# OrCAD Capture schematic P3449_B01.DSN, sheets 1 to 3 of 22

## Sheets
1 0021_Loop Back Test: size Custom
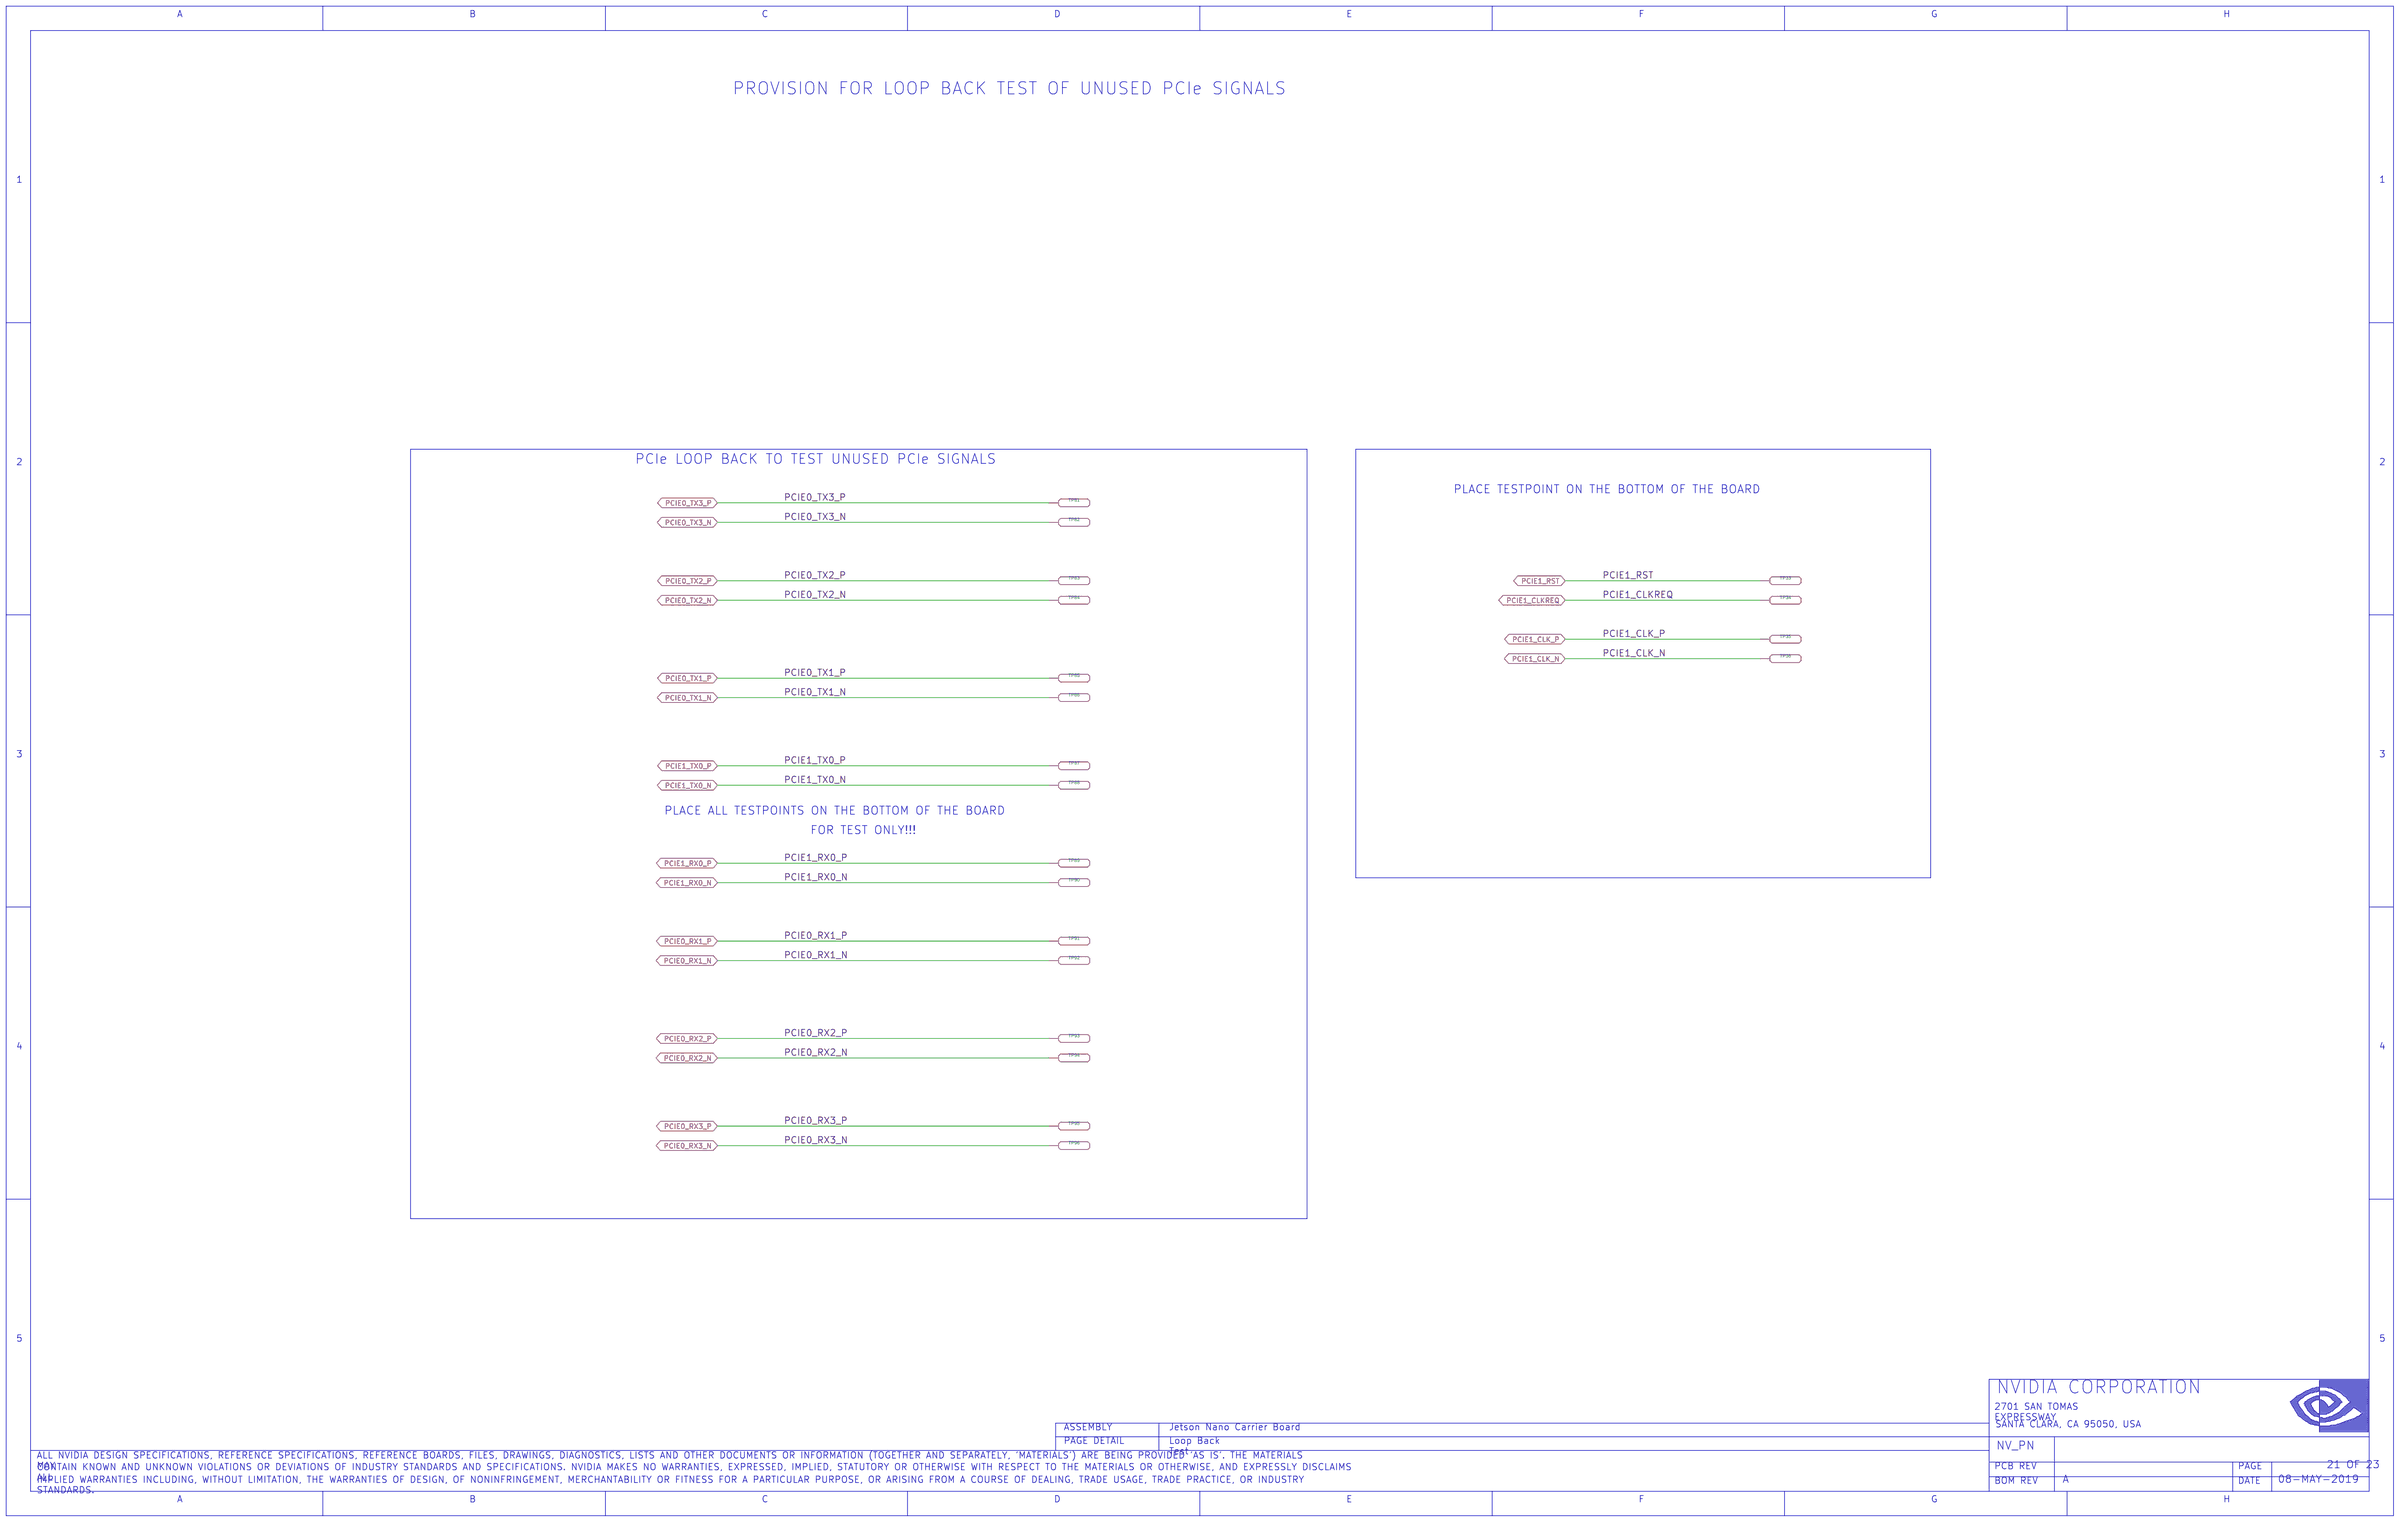
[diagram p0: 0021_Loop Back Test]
2 0020_Fan, Debug and EEPROM: size Custom
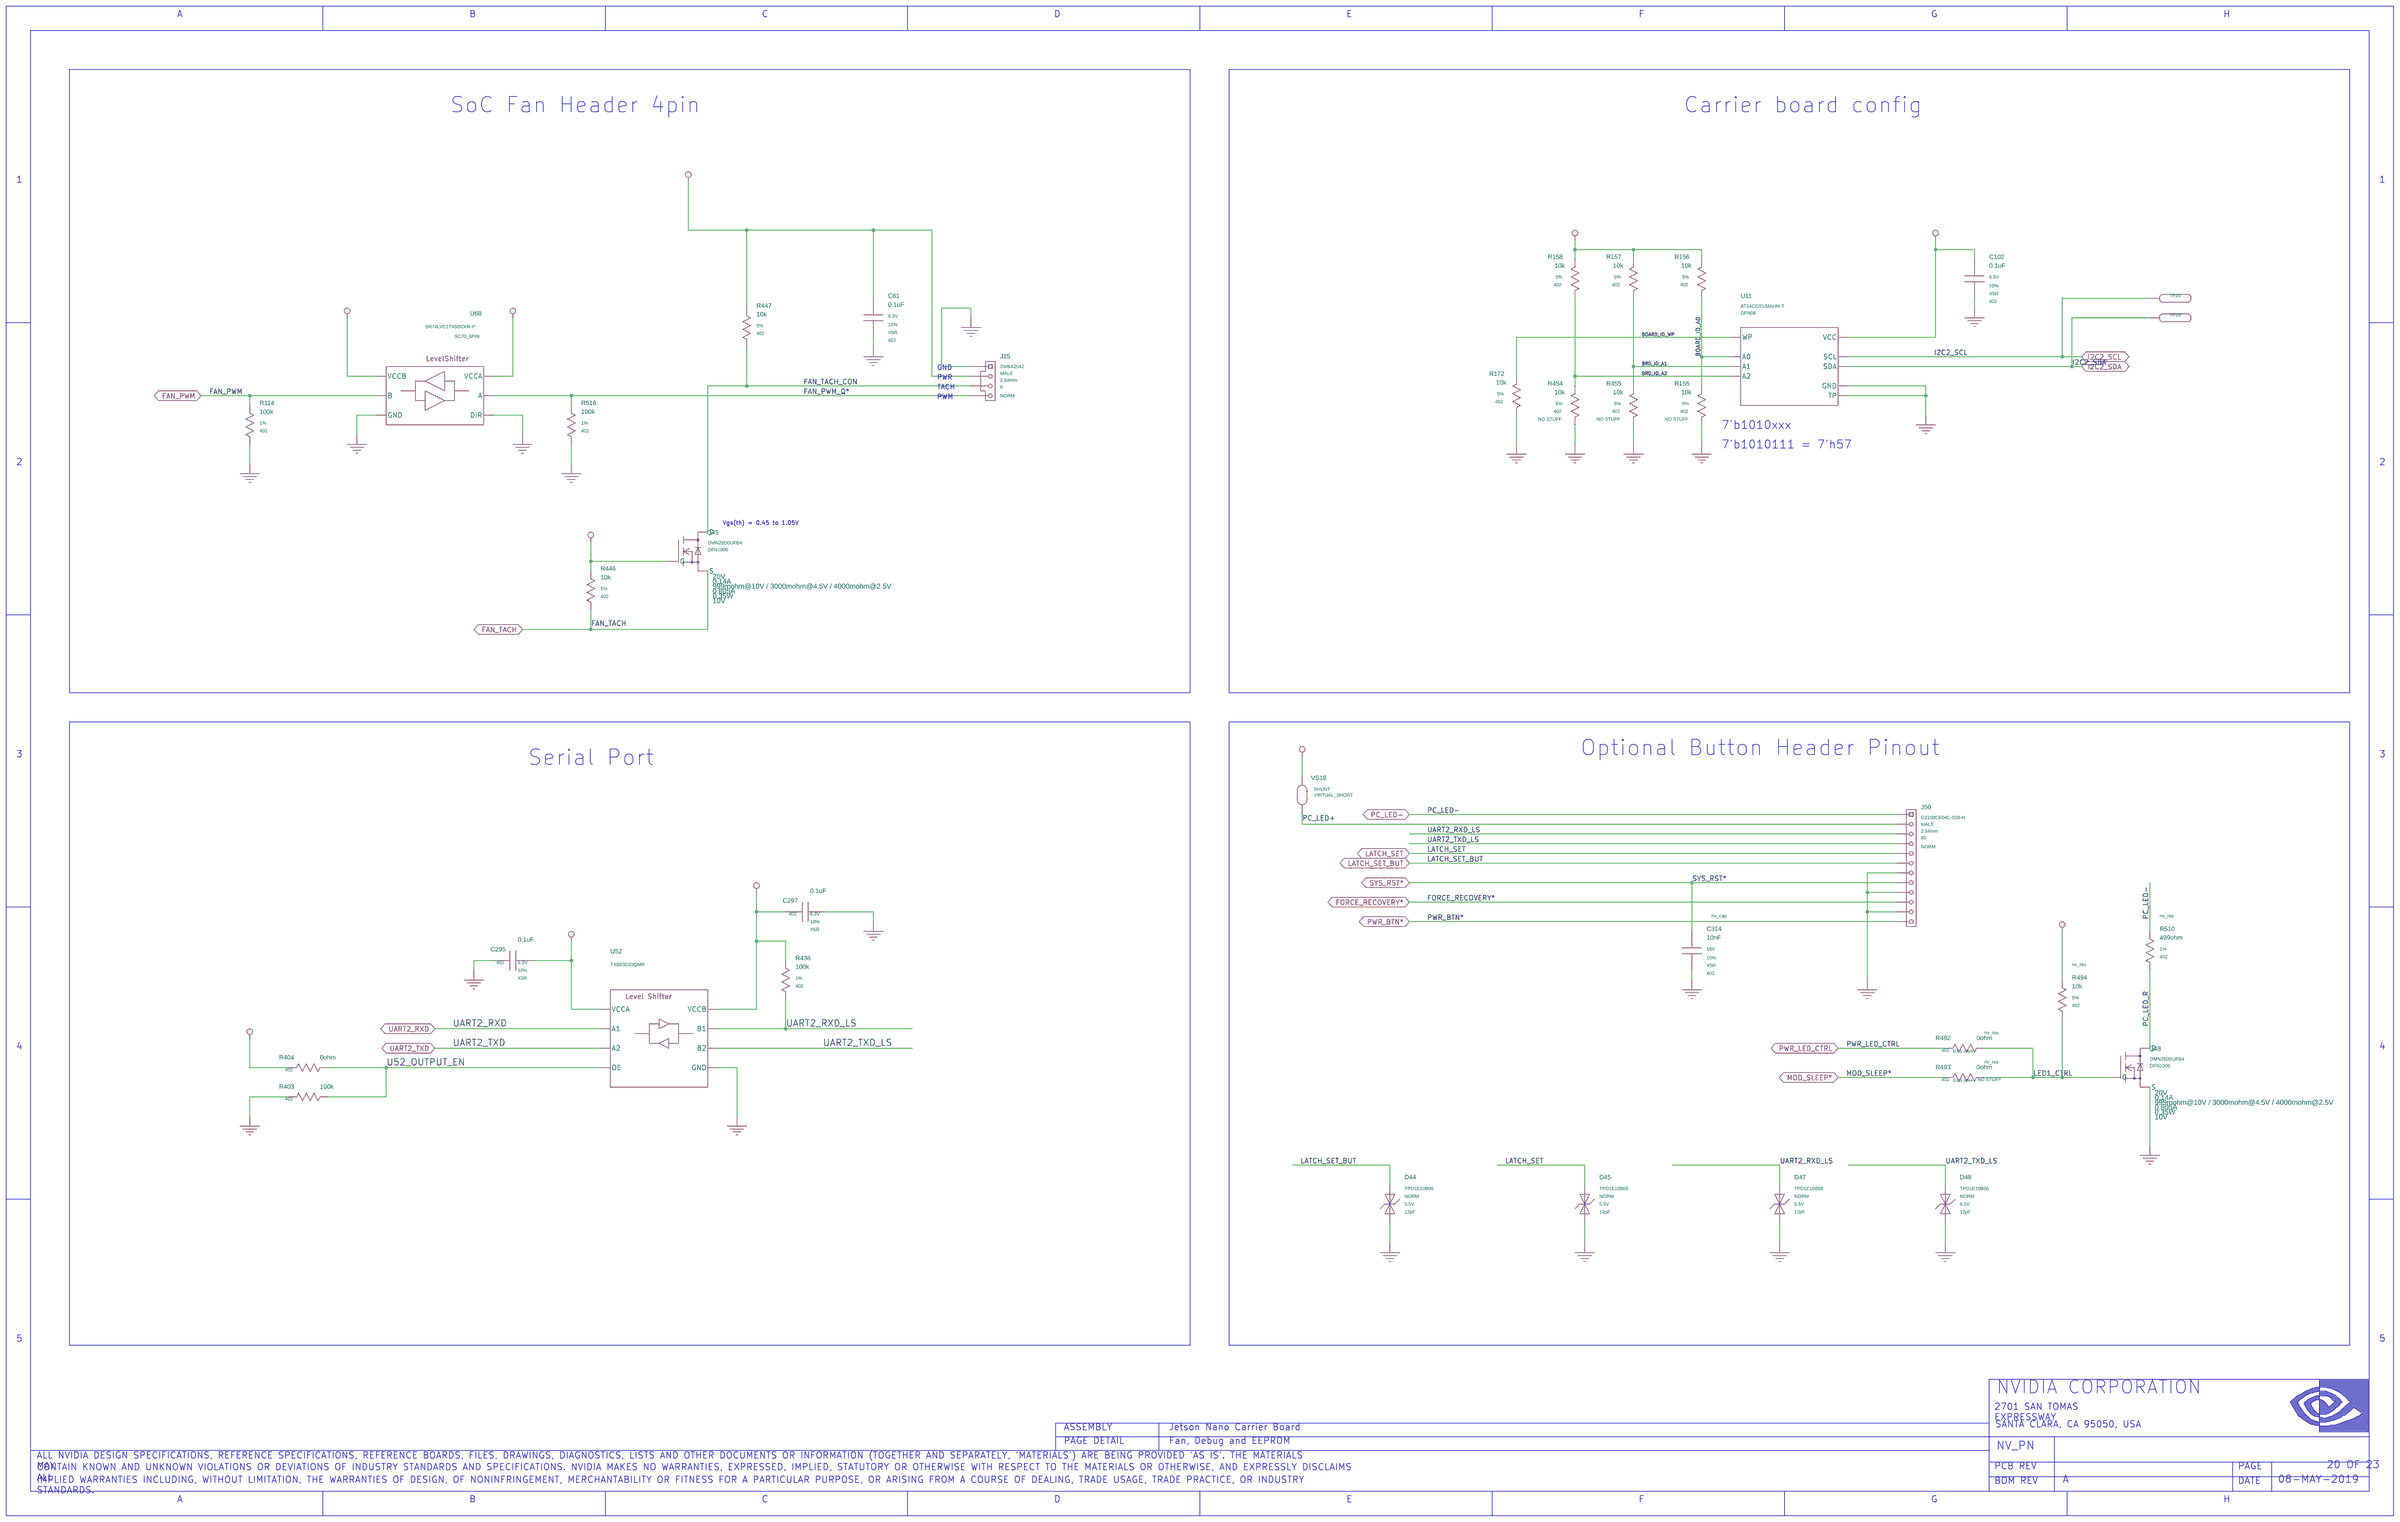
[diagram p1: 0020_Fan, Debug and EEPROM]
3 0019_40Pin GPIO expansion heade: size Custom
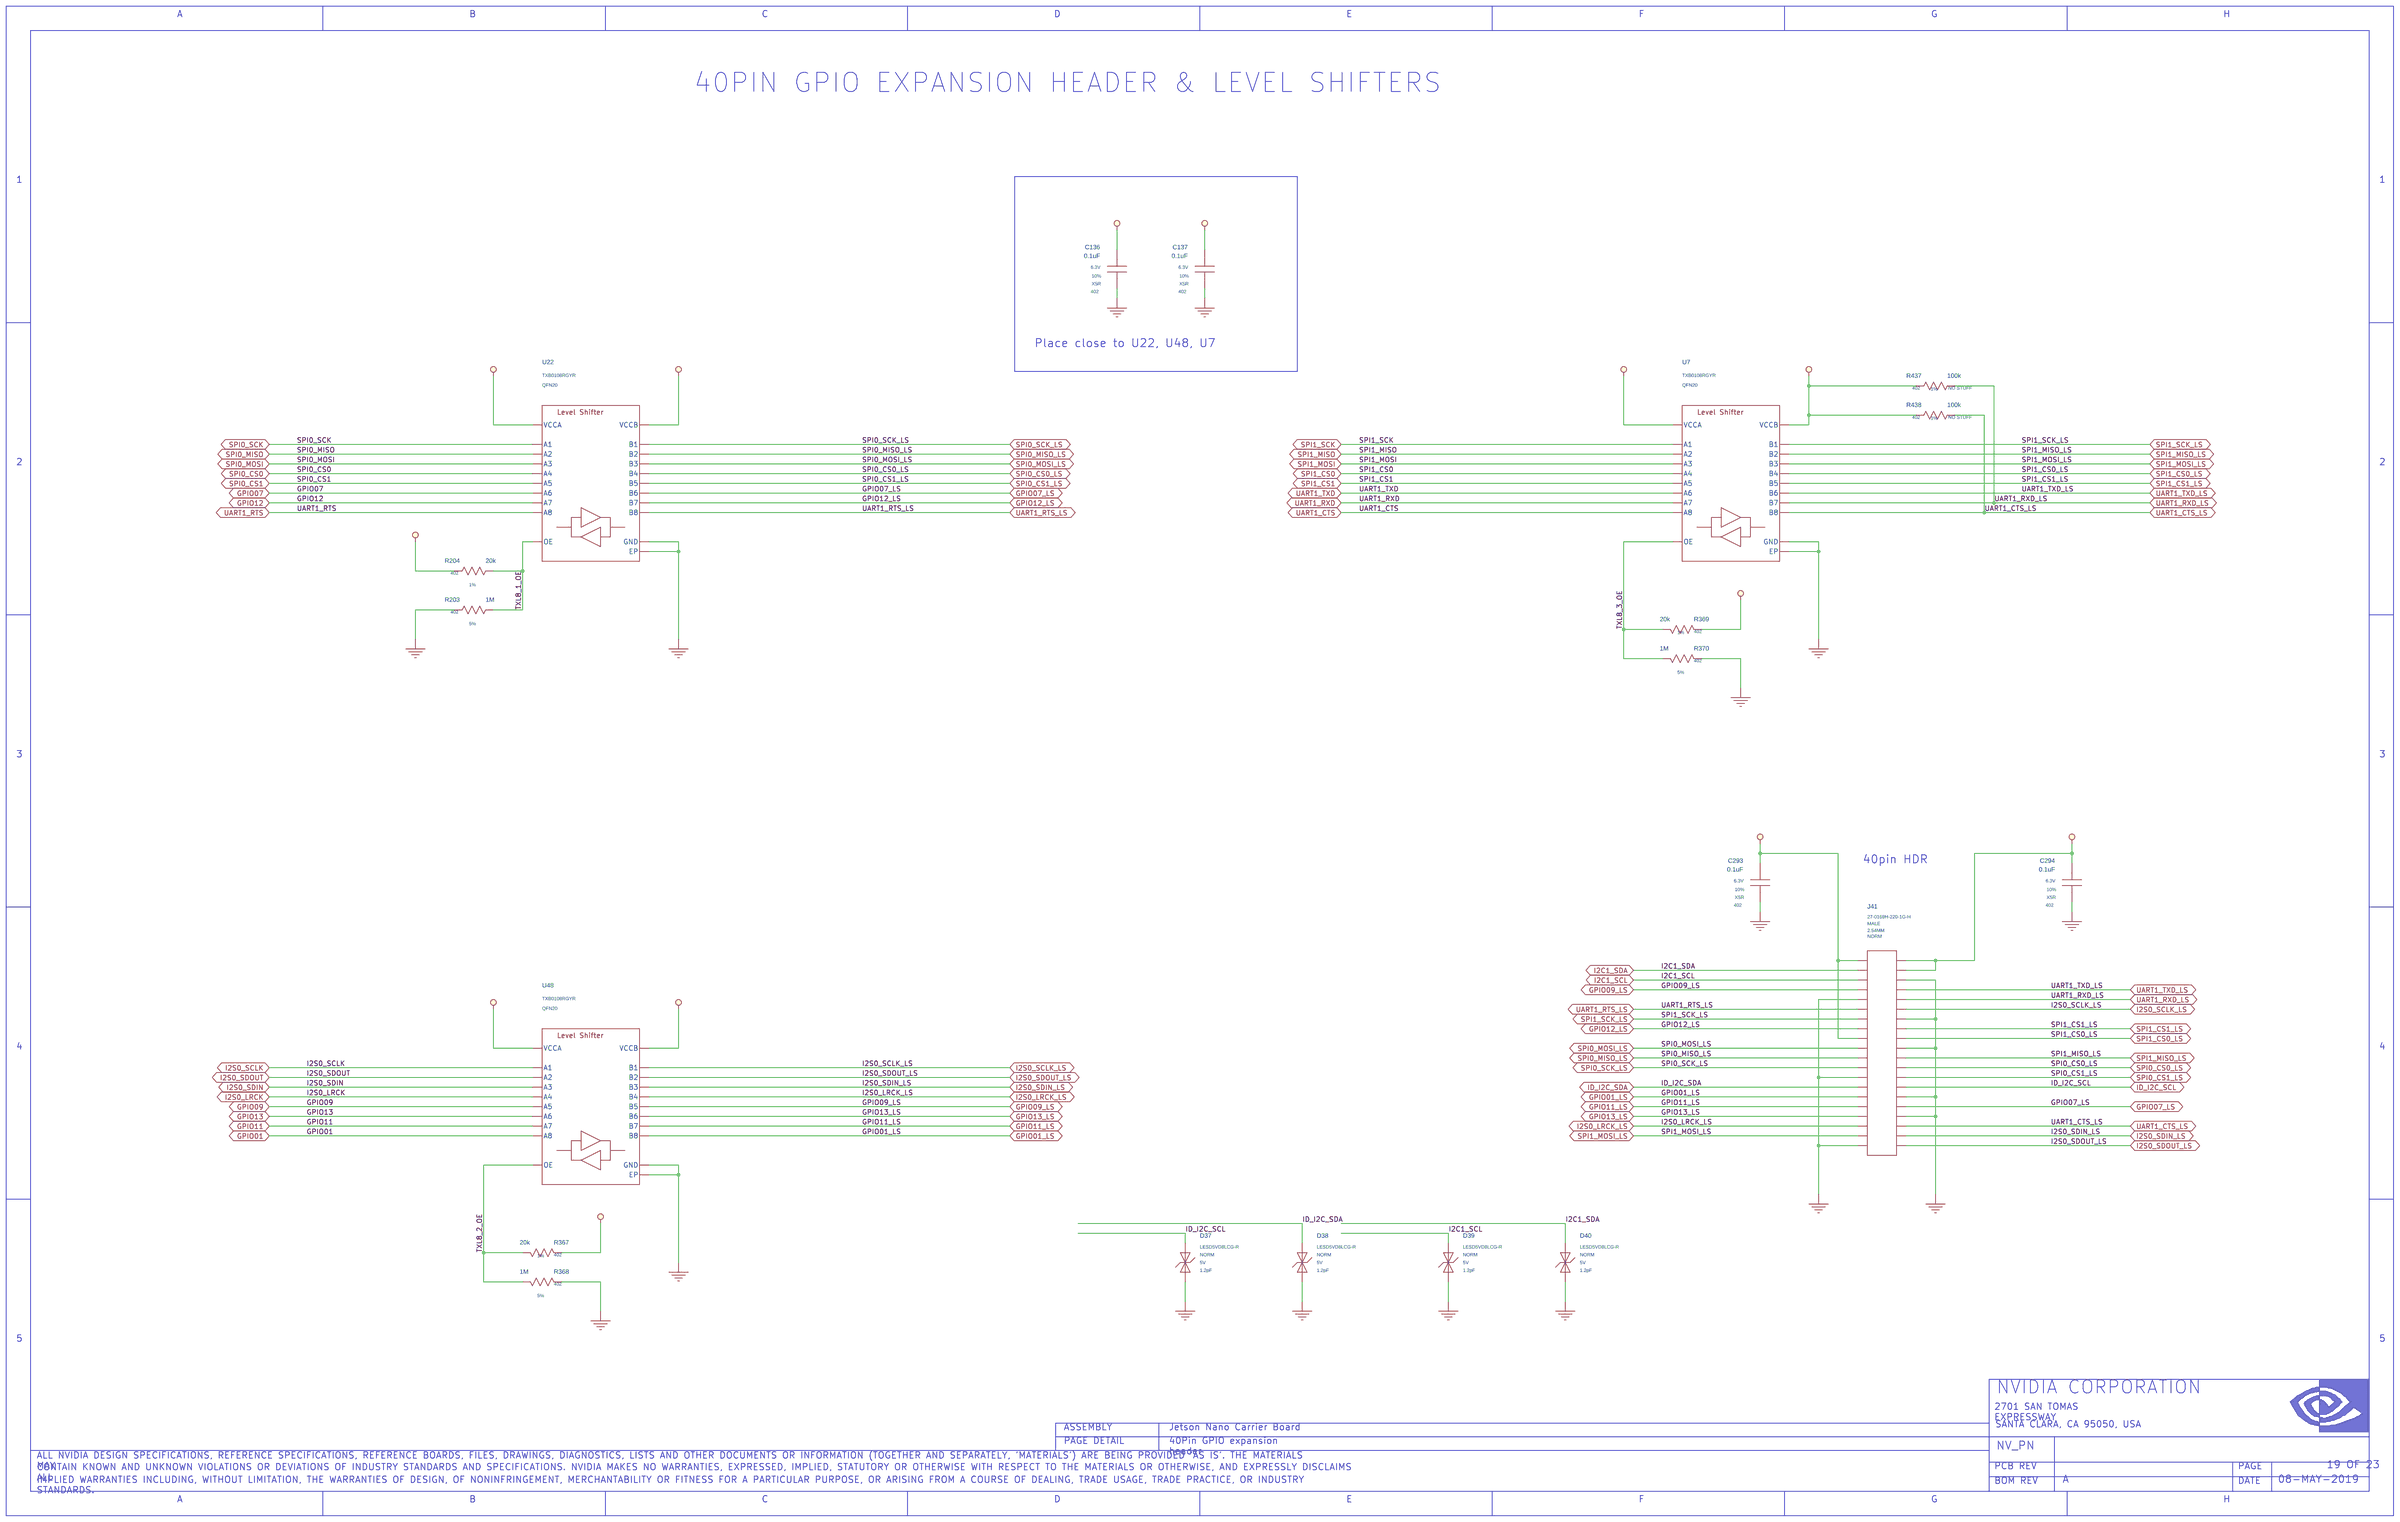
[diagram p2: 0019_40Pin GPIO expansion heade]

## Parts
sheet 0019_40Pin GPIO expansion heade
C136  0.1uF  [402]
C137  0.1uF  [402]
C293  0.1uF  [402]
C294  0.1uF  [402]
D37  D_ESD  [DIODE_SMD_010X060]
D38  D_ESD  [DIODE_SMD_010X060]
D39  D_ESD  [DIODE_SMD_010X060]
D40  D_ESD  [DIODE_SMD_010X060]
J41  HDR_2X20  [CON_HDR_002X020_TH_ST_M_P025_B]
R203  1M  [402]
R204  20k  [402]
R367  20k  [402]
R368  1M  [402]
R369  20k  [402]
R370  1M  [402]
R437  100k  [402]
R438  100k  [402]
U7  U_LEVSHFT_TXB0108  [QFN020R_P050_0045X0035_T031X021_VIAS]
U22  U_LEVSHFT_TXB0108  [QFN020R_P050_0045X0035_T031X021_VIAS]
U48  U_LEVSHFT_TXB0108  [QFN020R_P050_0045X0035_T031X021_VIAS]
sheet 0020_Fan, Debug and EEPROM
C61  0.1uF  [402]
C102  0.1uF  [402]
C295  0.1uF  [402]
C297  0.1uF  [402]
C314  10nF  [402]
D44  D_ESD  [DIODE_SMD_010X060]
D45  D_ESD  [DIODE_SMD_010X060]
D47  D_ESD  [DIODE_SMD_010X060]
D48  D_ESD  [DIODE_SMD_010X060]
J15  HDR_1X4  [CON_HDR_001X004_TH_ST_M_P025_B]
J50  HDR_1X12  [CON_HDR_001X012_TH_RA_M_P025]
Q45  Q_FET_N_ENH  [DFET_003_SMD_010X006_B]
Q48  Q_FET_N_ENH  [DFET_003_SMD_010X006_B]
R114  100k  [402]
R155  10k  [402]
R156  10k  [402]
R157  10k  [402]
R158  10k  [402]
R172  10k  [402]
R403  100k  [402]
R404  0ohm  [402]
R436  100k  [402]
R446  10k  [402]
R447  10k  [402]
R454  10k  [402]
R455  10k  [402]
R492  0ohm  [402]
R493  0ohm  [402]
R494  10k  [402]
R510  499ohm  [402]
R516  100k  [402]
TP19  LABTESTPOINT  [LTPB071C125D045C025P]
TP20  LABTESTPOINT  [LTPB071C125D045C025P]
U11  U_MEM_EE_I2C  [DFN08_P050_030X020_T016X016]
U52  U_LEVSHFT_TXB0302  [DFN08_P040_018X012]
U68  U_LEVSHFT_3STATE  [SC70_6]
VS18  VIRTUAL_SHORT  [VIRTUAL_SHORT]
sheet 0021_Loop Back Test
TP33  LABTESTPOINT  [LTPB071C125D045C025P]
TP34  LABTESTPOINT  [LTPB071C125D045C025P]
TP35  LABTESTPOINT  [LTPB071C125D045C025P]
TP36  LABTESTPOINT  [LTPB071C125D045C025P]
TP81  LABTESTPOINT  [LTPB071C125D045C025P]
TP82  LABTESTPOINT  [LTPB071C125D045C025P]
TP83  LABTESTPOINT  [LTPB071C125D045C025P]
TP84  LABTESTPOINT  [LTPB071C125D045C025P]
TP85  LABTESTPOINT  [LTPB071C125D045C025P]
TP86  LABTESTPOINT  [LTPB071C125D045C025P]
TP87  LABTESTPOINT  [LTPB071C125D045C025P]
TP88  LABTESTPOINT  [LTPB071C125D045C025P]
TP89  LABTESTPOINT  [LTPB071C125D045C025P]
TP90  LABTESTPOINT  [LTPB071C125D045C025P]
TP91  LABTESTPOINT  [LTPB071C125D045C025P]
TP92  LABTESTPOINT  [LTPB071C125D045C025P]
TP93  LABTESTPOINT  [LTPB071C125D045C025P]
TP94  LABTESTPOINT  [LTPB071C125D045C025P]
TP95  LABTESTPOINT  [LTPB071C125D045C025P]
TP96  LABTESTPOINT  [LTPB071C125D045C025P]

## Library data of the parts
C136 = C#1: ASSEMBLY: GPIO_HDR; CDS_LIB: discrete; CDS_PART_NAME: C_0402-0.1UF,X5R,10%,6.3V,039-0007-000; CDS_PHYS_PART_NAME: C_0402-0.1UF,X5R,10%,6.3V,039-0007-000-0.1UF,039-0007-000; CDS_SEC: 1; CHIPS_PART_NAME: C; DEVICE_TYPENAME: C_0402-01UFX5R1063V039-0007-000-01UF039-0007-000; DRAWING: @P3449_B01_LIB.P3449_B01(SCH_1):PAGE19; ESL: N/A; ESR: N/A; MAT: X5R; MAX_VOLTAGE: 6.3V; NV_PN: 039-0007-000; PATH: I119; PHYS_PAGE: 19; ROT: 2; SEC: 1; SIGNAL_MODEL: nv_cap; TOL: 10%; VER: 1; XY: (-6450,6250)
C137 = C#1: ASSEMBLY: GPIO_HDR; CDS_LIB: discrete; CDS_PART_NAME: C_0402-0.1UF,X5R,10%,6.3V,039-0007-000; CDS_PHYS_PART_NAME: C_0402-0.1UF,X5R,10%,6.3V,039-0007-000-0.1UF,039-0007-000; CDS_SEC: 1; CHIPS_PART_NAME: C; DEVICE_TYPENAME: C_0402-01UFX5R1063V039-0007-000-01UF039-0007-000; DRAWING: @P3449_B01_LIB.P3449_B01(SCH_1):PAGE19; ESL: N/A; ESR: N/A; MAT: X5R; MAX_VOLTAGE: 6.3V; NV_PN: 039-0007-000; PATH: I69; PHYS_PAGE: 19; ROT: 2; SEC: 1; SIGNAL_MODEL: nv_cap; TOL: 10%; VER: 1; XY: (-6000,6250)
C293 = C#1: ASSEMBLY: GPIO_HDR; CDS_LIB: discrete; CDS_PART_NAME: C_0402-0.1UF,X5R,10%,6.3V,039-0007-000; CDS_PHYS_PART_NAME: C_0402-0.1UF,X5R,10%,6.3V,039-0007-000-0.1UF,039-0007-000; CDS_SEC: 1; CHIPS_PART_NAME: C; DEVICE_TYPENAME: C_0402-01UFX5R1063V039-0007-000-01UF039-0007-000; DRAWING: @P3449_B01_LIB.P3449_B01(SCH_1):PAGE19; ESL: N/A; ESR: N/A; MAT: X5R; MAX_VOLTAGE: 6.3V; NV_PN: 039-0007-000; PATH: I267; PHYS_PAGE: 19; ROT: 2; SEC: 1; SIGNAL_MODEL: nv_cap; TOL: 10%; VER: 1; XY: (-3150,3100)
C294 = C#1: ASSEMBLY: GPIO_HDR; CDS_LIB: discrete; CDS_PART_NAME: C_0402-0.1UF,X5R,10%,6.3V,039-0007-000; CDS_PHYS_PART_NAME: C_0402-0.1UF,X5R,10%,6.3V,039-0007-000-0.1UF,039-0007-000; CDS_SEC: 1; CHIPS_PART_NAME: C; DEVICE_TYPENAME: C_0402-01UFX5R1063V039-0007-000-01UF039-0007-000; DRAWING: @P3449_B01_LIB.P3449_B01(SCH_1):PAGE19; ESL: N/A; ESR: N/A; MAT: X5R; MAX_VOLTAGE: 6.3V; NV_PN: 039-0007-000; PATH: I266; PHYS_PAGE: 19; ROT: 2; SEC: 1; SIGNAL_MODEL: nv_cap; TOL: 10%; VER: 1; XY: (-1550,3100)
D37 = D_ESD: ASSEMBLY: GPIO_HDR; BREAKDOWN_VOLTAGE_MIN_TYP: 5.5V; CAPACITANCE_MAX_TYP: 1.2pF; CDS_LIB: discrete; CDS_PART_NAME: D_ESD_NORM-LESD5VD8LCG-R,1 LINE,BI-DIRECTIONAL,5V,0.05UA,5.5V,10V@2A,1.2PF,090-0172-000; CDS_PHYS_PART_NAME: D_ESD_NORM-LESD5VD8LCG-R,1 LINE,BI-DIRECTIONAL,5V,0.05UA,5.5V,10V@2A,1.2PF,090-0172-000-090-0172-000; CDS_SEC: 1; CLAMPING_VOLTAGE: 10V@2A; CONFIGURATION: 1 Line; DEVICE_TYPENAME: D_ESD_NORM-LESD5VD8LCG-R1LINEBI-DIRECTIONAL5V005UA55V10V2A12PF090-0172-000-090-0172-000; DRAWING: @P3449_B01_LIB.P3449_B01(SCH_1):PAGE19; MAX_REVERSE_LEAKAGE_CURRENT: 0.05uA; MAX_REVERSE_VOLTAGE: 5V; NV_NAME: LESD5VD8LCG-R; NV_PN: 090-0172-000; PACK_TYPE: NORM; PATH: I279; PHYS_PAGE: 19; POLARITY: Bi-Directional; ROT: 0; SEC: 1; VER: 2; XY: (-6100,1150)
D38 = D_ESD: ASSEMBLY: GPIO_HDR; BREAKDOWN_VOLTAGE_MIN_TYP: 5.5V; CAPACITANCE_MAX_TYP: 1.2pF; CDS_LIB: discrete; CDS_PART_NAME: D_ESD_NORM-LESD5VD8LCG-R,1 LINE,BI-DIRECTIONAL,5V,0.05UA,5.5V,10V@2A,1.2PF,090-0172-000; CDS_PHYS_PART_NAME: D_ESD_NORM-LESD5VD8LCG-R,1 LINE,BI-DIRECTIONAL,5V,0.05UA,5.5V,10V@2A,1.2PF,090-0172-000-090-0172-000; CDS_SEC: 1; CLAMPING_VOLTAGE: 10V@2A; CONFIGURATION: 1 Line; DEVICE_TYPENAME: D_ESD_NORM-LESD5VD8LCG-R1LINEBI-DIRECTIONAL5V005UA55V10V2A12PF090-0172-000-090-0172-000; DRAWING: @P3449_B01_LIB.P3449_B01(SCH_1):PAGE19; MAX_REVERSE_LEAKAGE_CURRENT: 0.05uA; MAX_REVERSE_VOLTAGE: 5V; NV_NAME: LESD5VD8LCG-R; NV_PN: 090-0172-000; PACK_TYPE: NORM; PATH: I278; PHYS_PAGE: 19; POLARITY: Bi-Directional; ROT: 0; SEC: 1; VER: 2; XY: (-5500,1150)
D39 = D_ESD: ASSEMBLY: GPIO_HDR; BREAKDOWN_VOLTAGE_MIN_TYP: 5.5V; CAPACITANCE_MAX_TYP: 1.2pF; CDS_LIB: discrete; CDS_PART_NAME: D_ESD_NORM-LESD5VD8LCG-R,1 LINE,BI-DIRECTIONAL,5V,0.05UA,5.5V,10V@2A,1.2PF,090-0172-000; CDS_PHYS_PART_NAME: D_ESD_NORM-LESD5VD8LCG-R,1 LINE,BI-DIRECTIONAL,5V,0.05UA,5.5V,10V@2A,1.2PF,090-0172-000-090-0172-000; CDS_SEC: 1; CLAMPING_VOLTAGE: 10V@2A; CONFIGURATION: 1 Line; DEVICE_TYPENAME: D_ESD_NORM-LESD5VD8LCG-R1LINEBI-DIRECTIONAL5V005UA55V10V2A12PF090-0172-000-090-0172-000; DRAWING: @P3449_B01_LIB.P3449_B01(SCH_1):PAGE19; MAX_REVERSE_LEAKAGE_CURRENT: 0.05uA; MAX_REVERSE_VOLTAGE: 5V; NV_NAME: LESD5VD8LCG-R; NV_PN: 090-0172-000; PACK_TYPE: NORM; PATH: I274; PHYS_PAGE: 19; POLARITY: Bi-Directional; ROT: 0; SEC: 1; VER: 2; XY: (-4750,1150)
D40 = D_ESD: ASSEMBLY: GPIO_HDR; BREAKDOWN_VOLTAGE_MIN_TYP: 5.5V; CAPACITANCE_MAX_TYP: 1.2pF; CDS_LIB: discrete; CDS_PART_NAME: D_ESD_NORM-LESD5VD8LCG-R,1 LINE,BI-DIRECTIONAL,5V,0.05UA,5.5V,10V@2A,1.2PF,090-0172-000; CDS_PHYS_PART_NAME: D_ESD_NORM-LESD5VD8LCG-R,1 LINE,BI-DIRECTIONAL,5V,0.05UA,5.5V,10V@2A,1.2PF,090-0172-000-090-0172-000; CDS_SEC: 1; CLAMPING_VOLTAGE: 10V@2A; CONFIGURATION: 1 Line; DEVICE_TYPENAME: D_ESD_NORM-LESD5VD8LCG-R1LINEBI-DIRECTIONAL5V005UA55V10V2A12PF090-0172-000-090-0172-000; DRAWING: @P3449_B01_LIB.P3449_B01(SCH_1):PAGE19; MAX_REVERSE_LEAKAGE_CURRENT: 0.05uA; MAX_REVERSE_VOLTAGE: 5V; NV_NAME: LESD5VD8LCG-R; NV_PN: 090-0172-000; PACK_TYPE: NORM; PATH: I275; PHYS_PAGE: 19; POLARITY: Bi-Directional; ROT: 0; SEC: 1; VER: 2; XY: (-4150,1150)
J41 = HDR_2X20: ANGLE: 0; ASSEMBLY: GPIO_HDR; CDS_LIB: electro_mechanic; CDS_PART_NAME: HDR_2X20_NORM-27-0169H-220-1G-H,MALE,2.54MM,0,YES,NO,NO,1000 V,3 A,074-0221-000; CDS_PHYS_PART_NAME: HDR_2X20_NORM-27-0169H-220-1G-H,MALE,2.54MM,0,YES,NO,NO,1000 V,3 A,074-0221-000-074-0221-000; CDS_SEC: 1; DEVICE_TYPENAME: HDR_2X20_NORM-27-0169H-220-1G-HMALE254MM0YESNONO1000V3A074-0221-000-074-0221-000; DRAWING: @P3449_B01_LIB.P3449_B01(SCH_1):PAGE19; GENDER: MALE; LATCHING: NO; MAX_CURRENT: 3:00 上午; MAX_VOLTAGE: 1000 V; NV_NAME: 27-0169H-220-1G-H; NV_PN: 074-0221-000; PACK_TYPE: NORM; PATH: I68; PHYS_PAGE: 19; PITCH: 2.54MM; REFLOW: YES; ROT: 0; SEC: 1; SEC_TYPE: NORM; SHROUDED: NO; VER: 1; XY: (-2500,2200)
R203 = R#1: ASSEMBLY: GPIO_HDR; CDS_LIB: discrete; CDS_PART_NAME: R_0402-1M,5 %,62.5MW,195-0488-000; CDS_PHYS_PART_NAME: R_0402-1M,5 %,62.5MW,195-0488-000-195-0488-000,1M; CDS_SEC: 1; CHIPS_PART_NAME: R; DEVICE_TYPENAME: R_0402-1M5625MW195-0488-000-195-0488-0001M; DRAWING: @P3449_B01_LIB.P3449_B01(SCH_1):PAGE19; MAX_WATTAGE: 62.5mW; NV_PN: 195-0488-000; PATH: I118; PHYS_PAGE: 19; ROT: 0; SEC: 1; SIGNAL_MODEL: nv_res; TOL: 5%; VER: 1; XY: (-9750,4500)
R204 = R#1: ASSEMBLY: GPIO_HDR; CDS_LIB: discrete; CDS_PART_NAME: R_0402-20K,1 %,62.5MW,195-0150-000; CDS_PHYS_PART_NAME: R_0402-20K,1 %,62.5MW,195-0150-000-195-0150-000,20K; CDS_SEC: 1; CHIPS_PART_NAME: R; DEVICE_TYPENAME: R_0402-20K1625MW195-0150-000-195-0150-00020K; DRAWING: @P3449_B01_LIB.P3449_B01(SCH_1):PAGE19; MAX_WATTAGE: 62.5mW; NV_PN: 195-0150-000; PATH: I117; PHYS_PAGE: 19; ROT: 0; SEC: 1; SIGNAL_MODEL: nv_res; TOL: 1%; VER: 1; XY: (-9750,4700)
R367 = R#1: ASSEMBLY: GPIO_HDR; CDS_LIB: discrete; CDS_PART_NAME: R_0402-20K,1 %,62.5MW,195-0150-000; CDS_PHYS_PART_NAME: R_0402-20K,1 %,62.5MW,195-0150-000-195-0150-000,20K; CDS_SEC: 1; CHIPS_PART_NAME: R; DEVICE_TYPENAME: R_0402-20K1625MW195-0150-000-195-0150-00020K; DRAWING: @P3449_B01_LIB.P3449_B01(SCH_1):PAGE19; MAX_WATTAGE: 62.5mW; NV_PN: 195-0150-000; PATH: I90; PHYS_PAGE: 19; ROT: 2; SEC: 1; SIGNAL_MODEL: nv_res; TOL: 1%; VER: 1; XY: (-9400,1200)
R368 = R#1: ASSEMBLY: GPIO_HDR; CDS_LIB: discrete; CDS_PART_NAME: R_0402-1M,5 %,62.5MW,195-0488-000; CDS_PHYS_PART_NAME: R_0402-1M,5 %,62.5MW,195-0488-000-195-0488-000,1M; CDS_SEC: 1; CHIPS_PART_NAME: R; DEVICE_TYPENAME: R_0402-1M5625MW195-0488-000-195-0488-0001M; DRAWING: @P3449_B01_LIB.P3449_B01(SCH_1):PAGE19; MAX_WATTAGE: 62.5mW; NV_PN: 195-0488-000; PATH: I91; PHYS_PAGE: 19; ROT: 2; SEC: 1; SIGNAL_MODEL: nv_res; TOL: 5%; VER: 1; XY: (-9400,1050)
R369 = R#1: ASSEMBLY: GPIO_HDR; CDS_LIB: discrete; CDS_PART_NAME: R_0402-20K,1 %,62.5MW,195-0150-000; CDS_PHYS_PART_NAME: R_0402-20K,1 %,62.5MW,195-0150-000-195-0150-000,20K; CDS_SEC: 1; CHIPS_PART_NAME: R; DEVICE_TYPENAME: R_0402-20K1625MW195-0150-000-195-0150-00020K; DRAWING: @P3449_B01_LIB.P3449_B01(SCH_1):PAGE19; MAX_WATTAGE: 62.5mW; NV_PN: 195-0150-000; PATH: I150; PHYS_PAGE: 19; ROT: 2; SEC: 1; SIGNAL_MODEL: nv_res; TOL: 1%; VER: 1; XY: (-3550,4400)
R370 = R#1: ASSEMBLY: GPIO_HDR; CDS_LIB: discrete; CDS_PART_NAME: R_0402-1M,5 %,62.5MW,195-0488-000; CDS_PHYS_PART_NAME: R_0402-1M,5 %,62.5MW,195-0488-000-195-0488-000,1M; CDS_SEC: 1; CHIPS_PART_NAME: R; DEVICE_TYPENAME: R_0402-1M5625MW195-0488-000-195-0488-0001M; DRAWING: @P3449_B01_LIB.P3449_B01(SCH_1):PAGE19; MAX_WATTAGE: 62.5mW; NV_PN: 195-0488-000; PATH: I151; PHYS_PAGE: 19; ROT: 2; SEC: 1; SIGNAL_MODEL: nv_res; TOL: 5%; VER: 1; XY: (-3550,4250)
R437 = R#1: ASSEMBLY: GPIO_HDR; CDS_LIB: discrete; CDS_PART_NAME: R_0402-100K,1 %,62.5MW,195-0005-000; CDS_PHYS_PART_NAME: R_0402-100K,1 %,62.5MW,195-0005-000-100K,195-0005-000; CDS_SEC: 1; CHIPS_PART_NAME: R; DEVICE_TYPENAME: R_0402-100K1625MW195-0005-000-100K195-0005-000; DRAWING: @P3449_B01_LIB.P3449_B01(SCH_1):PAGE19; MAX_WATTAGE: 62.5mW; NV_PN: 195-0005-000; PATH: I272; PHYS_PAGE: 19; ROT: 0; SEC: 1; SIGNAL_MODEL: nv_res; SKU: NO STUFF; TOL: 1%; VER: 1; XY: (-2250,5650)
R438 = R#1: ASSEMBLY: GPIO_HDR; CDS_LIB: discrete; CDS_PART_NAME: R_0402-100K,1 %,62.5MW,195-0005-000; CDS_PHYS_PART_NAME: R_0402-100K,1 %,62.5MW,195-0005-000-100K,195-0005-000; CDS_SEC: 1; CHIPS_PART_NAME: R; DEVICE_TYPENAME: R_0402-100K1625MW195-0005-000-100K195-0005-000; DRAWING: @P3449_B01_LIB.P3449_B01(SCH_1):PAGE19; MAX_WATTAGE: 62.5mW; NV_PN: 195-0005-000; PATH: I273; PHYS_PAGE: 19; ROT: 0; SEC: 1; SIGNAL_MODEL: nv_res; SKU: NO STUFF; TOL: 1%; VER: 1; XY: (-2250,5500)
U7 = U_LEVSHFT_TXB0108: ASSEMBLY: GPIO_HDR; CDS_LIB: digital; CDS_PART_NAME: U_LEVSHFT_TXB0108_QFN20-TXB0108RGYR,LEVEL SHIFTER,115-1921-000; CDS_PHYS_PART_NAME: U_LEVSHFT_TXB0108_QFN20-TXB0108RGYR,LEVEL SHIFTER,115-1921-000-115-1921-000; CDS_SEC: 1; DEVICE_TYPENAME: U_LEVSHFT_TXB0108_QFN20-TXB0108RGYRLEVELSHIFTER115-1921-000-115-1921-000; DRAWING: @P3449_B01_LIB.P3449_B01(SCH_1):PAGE19; FUNCTION: Level Shifter; NV_NAME: TXB0108RGYR; NV_PN: 115-1921-000; PACK_TYPE: QFN20; PATH: I140; PHYS_PAGE: 19; ROT: 0; SEC: 1; SEC_TYPE: QFN20; VER: 1; XY: (-3300,5200)
U22 = U_LEVSHFT_TXB0108: ASSEMBLY: GPIO_HDR; CDS_LIB: digital; CDS_PART_NAME: U_LEVSHFT_TXB0108_QFN20-TXB0108RGYR,LEVEL SHIFTER,115-1921-000; CDS_PHYS_PART_NAME: U_LEVSHFT_TXB0108_QFN20-TXB0108RGYR,LEVEL SHIFTER,115-1921-000-115-1921-000; CDS_SEC: 1; DEVICE_TYPENAME: U_LEVSHFT_TXB0108_QFN20-TXB0108RGYRLEVELSHIFTER115-1921-000-115-1921-000; DRAWING: @P3449_B01_LIB.P3449_B01(SCH_1):PAGE19; FUNCTION: Level Shifter; NV_NAME: TXB0108RGYR; NV_PN: 115-1921-000; PACK_TYPE: QFN20; PATH: I116; PHYS_PAGE: 19; ROT: 0; SEC: 1; SEC_TYPE: QFN20; VER: 1; XY: (-9150,5200)
U48 = U_LEVSHFT_TXB0108: ASSEMBLY: GPIO_HDR; CDS_LIB: digital; CDS_PART_NAME: U_LEVSHFT_TXB0108_QFN20-TXB0108RGYR,LEVEL SHIFTER,115-1921-000; CDS_PHYS_PART_NAME: U_LEVSHFT_TXB0108_QFN20-TXB0108RGYR,LEVEL SHIFTER,115-1921-000-115-1921-000; CDS_SEC: 1; DEVICE_TYPENAME: U_LEVSHFT_TXB0108_QFN20-TXB0108RGYRLEVELSHIFTER115-1921-000-115-1921-000; DRAWING: @P3449_B01_LIB.P3449_B01(SCH_1):PAGE19; FUNCTION: Level Shifter; NV_NAME: TXB0108RGYR; NV_PN: 115-1921-000; PACK_TYPE: QFN20; PATH: I89; PHYS_PAGE: 19; ROT: 0; SEC: 1; SEC_TYPE: QFN20; VER: 1; XY: (-9150,2000)
C61 = C#1: ASSEMBLY: FAN; CDS_LIB: discrete; CDS_PART_NAME: C_0402-0.1UF,X5R,10%,6.3V,039-0007-000; CDS_PHYS_PART_NAME: C_0402-0.1UF,X5R,10%,6.3V,039-0007-000-0.1UF,039-0007-000; CDS_SEC: 1; CHIPS_PART_NAME: C; DEVICE_TYPENAME: C_0402-01UFX5R1063V039-0007-000-01UF039-0007-000; DRAWING: @P3449_B01_LIB.P3449_B01(SCH_1):PAGE20; MAT: X5R; MAX_VOLTAGE: 6.3V; NV_PN: 039-0007-000; PATH: I22; PHYS_PAGE: 20; ROT: 0; SEC: 1; SIGNAL_MODEL: nv_cap; TOL: 10%; VER: 1; XY: (-7700,6000)
C102 = C#1: ASSEMBLY: L4T_EEPROM; CDS_LIB: discrete; CDS_PART_NAME: C_0402-0.1UF,X5R,10%,6.3V,039-0007-000; CDS_PHYS_PART_NAME: C_0402-0.1UF,X5R,10%,6.3V,039-0007-000-0.1UF,039-0007-000; CDS_SEC: 1; CHIPS_PART_NAME: C; DEVICE_TYPENAME: C_0402-01UFX5R1063V039-0007-000-01UF039-0007-000; DRAWING: @P3449_B01_LIB.P3449_B01(SCH_1):PAGE20; MAT: X5R; MAX_VOLTAGE: 6.3V; NV_PN: 039-0007-000; PATH: I341; PHYS_PAGE: 20; ROT: 0; SEC: 1; SIGNAL_MODEL: nv_cap; TOL: 10%; VER: 1; XY: (-2050,6200)
C295 = C: ASSEMBLY: DEBUG; CDS_LIB: discrete; CDS_PART_NAME: C_0402-0.1UF,X5R,10%,6.3V,039-0007-000; CDS_PHYS_PART_NAME: C_0402-0.1UF,X5R,10%,6.3V,039-0007-000-0.1UF,039-0007-000; CDS_SEC: 1; DEVICE_TYPENAME: C_0402-01UFX5R1063V039-0007-000-01UF039-0007-000; DRAWING: @P3449_B01_LIB.P3449_B01(SCH_1):PAGE20; MAT: X5R; MAX_VOLTAGE: 6.3V; NV_PN: 039-0007-000; PATH: I309; PHYS_PAGE: 20; ROT: 0; SEC: 1; SIGNAL_MODEL: nv_cap; TOL: 10%; VER: 2; XY: (-9550,2700)
C297 = C: ASSEMBLY: DEBUG; CDS_LIB: discrete; CDS_PART_NAME: C_0402-0.1UF,X5R,10%,6.3V,039-0007-000; CDS_PHYS_PART_NAME: C_0402-0.1UF,X5R,10%,6.3V,039-0007-000-0.1UF,039-0007-000; CDS_SEC: 1; DEVICE_TYPENAME: C_0402-01UFX5R1063V039-0007-000-01UF039-0007-000; DRAWING: @P3449_B01_LIB.P3449_B01(SCH_1):PAGE20; MAT: X5R; MAX_VOLTAGE: 6.3V; NV_PN: 039-0007-000; PATH: I307; PHYS_PAGE: 20; ROT: 0; SEC: 1; SIGNAL_MODEL: nv_cap; TOL: 10%; VER: 2; XY: (-8050,2950)
C314 = C#1: ASSEMBLY: AUTOMATION; CDS_LIB: discrete; CDS_PART_NAME: C_0402-10NF,X5R,10%,16V,039-0024-000; CDS_PHYS_PART_NAME: C_0402-10NF,X5R,10%,16V,039-0024-000-039-0024-000,10NF; CDS_SEC: 1; CHIPS_PART_NAME: C; DEVICE_TYPENAME: C_0402-10NFX5R1016V039-0024-000-039-0024-00010NF; DRAWING: @P3449_B01_LIB.P3449_B01(SCH_1):PAGE20; MAT: X5R; MAX_VOLTAGE: 16V; NV_PN: 039-0024-000; PATH: I402; PHYS_PAGE: 20; ROT: 0; SEC: 1; SIGNAL_MODEL: nv_cap; TOL: 10%; VER: 1; XY: (-3500,2750)
D44 = D_ESD: ASSEMBLY: AUTOMATION; BREAKDOWN_VOLTAGE_MIN_TYP: 6V; CAPACITANCE_MAX_TYP: 12pF; CDS_LIB: discrete; CDS_PART_NAME: D_ESD_NORM-TPD1E10B06,1 LINE,BI-DIRECTIONAL,5.5V,0.1UA,6V,10V@1A,12PF,090-0243-000; CDS_PHYS_PART_NAME: D_ESD_NORM-TPD1E10B06,1 LINE,BI-DIRECTIONAL,5.5V,0.1UA,6V,10V@1A,12PF,090-0243-000-090-0243-000; CDS_SEC: 1; CLAMPING_VOLTAGE: 10V@1A; CONFIGURATION: 1 Line; DEVICE_TYPENAME: D_ESD_NORM-TPD1E10B061LINEBI-DIRECTIONAL55V01UA6V10V1A12PF090-0243-000-090-0243-000; DRAWING: @P3449_B01_LIB.P3449_B01(SCH_1):PAGE20; MAX_REVERSE_LEAKAGE_CURRENT: 0.1uA; MAX_REVERSE_VOLTAGE: 5.5V; NV_NAME: TPD1E10B06; NV_PN: 090-0243-000; PACK_TYPE: NORM; PATH: I396; PHYS_PAGE: 20; POLARITY: Bi-Directional; ROT: 0; SEC: 1; VER: 2; XY: (-5050,1450)
D45 = D_ESD: ASSEMBLY: AUTOMATION; BREAKDOWN_VOLTAGE_MIN_TYP: 6V; CAPACITANCE_MAX_TYP: 12pF; CDS_LIB: discrete; CDS_PART_NAME: D_ESD_NORM-TPD1E10B06,1 LINE,BI-DIRECTIONAL,5.5V,0.1UA,6V,10V@1A,12PF,090-0243-000; CDS_PHYS_PART_NAME: D_ESD_NORM-TPD1E10B06,1 LINE,BI-DIRECTIONAL,5.5V,0.1UA,6V,10V@1A,12PF,090-0243-000-090-0243-000; CDS_SEC: 1; CLAMPING_VOLTAGE: 10V@1A; CONFIGURATION: 1 Line; DEVICE_TYPENAME: D_ESD_NORM-TPD1E10B061LINEBI-DIRECTIONAL55V01UA6V10V1A12PF090-0243-000-090-0243-000; DRAWING: @P3449_B01_LIB.P3449_B01(SCH_1):PAGE20; MAX_REVERSE_LEAKAGE_CURRENT: 0.1uA; MAX_REVERSE_VOLTAGE: 5.5V; NV_NAME: TPD1E10B06; NV_PN: 090-0243-000; PACK_TYPE: NORM; PATH: I399; PHYS_PAGE: 20; POLARITY: Bi-Directional; ROT: 0; SEC: 1; VER: 2; XY: (-4050,1450)
D47 = D_ESD: ASSEMBLY: AUTOMATION; BREAKDOWN_VOLTAGE_MIN_TYP: 6V; CAPACITANCE_MAX_TYP: 12pF; CDS_LIB: discrete; CDS_PART_NAME: D_ESD_NORM-TPD1E10B06,1 LINE,BI-DIRECTIONAL,5.5V,0.1UA,6V,10V@1A,12PF,090-0243-000; CDS_PHYS_PART_NAME: D_ESD_NORM-TPD1E10B06,1 LINE,BI-DIRECTIONAL,5.5V,0.1UA,6V,10V@1A,12PF,090-0243-000-090-0243-000; CDS_SEC: 1; CLAMPING_VOLTAGE: 10V@1A; CONFIGURATION: 1 Line; DEVICE_TYPENAME: D_ESD_NORM-TPD1E10B061LINEBI-DIRECTIONAL55V01UA6V10V1A12PF090-0243-000-090-0243-000; DRAWING: @P3449_B01_LIB.P3449_B01(SCH_1):PAGE20; MAX_REVERSE_LEAKAGE_CURRENT: 0.1uA; MAX_REVERSE_VOLTAGE: 5.5V; NV_NAME: TPD1E10B06; NV_PN: 090-0243-000; PACK_TYPE: NORM; PATH: I392; PHYS_PAGE: 20; POLARITY: Bi-Directional; ROT: 0; SEC: 1; VER: 2; XY: (-3050,1450)
D48 = D_ESD: ASSEMBLY: AUTOMATION; BREAKDOWN_VOLTAGE_MIN_TYP: 6V; CAPACITANCE_MAX_TYP: 12pF; CDS_LIB: discrete; CDS_PART_NAME: D_ESD_NORM-TPD1E10B06,1 LINE,BI-DIRECTIONAL,5.5V,0.1UA,6V,10V@1A,12PF,090-0243-000; CDS_PHYS_PART_NAME: D_ESD_NORM-TPD1E10B06,1 LINE,BI-DIRECTIONAL,5.5V,0.1UA,6V,10V@1A,12PF,090-0243-000-090-0243-000; CDS_SEC: 1; CLAMPING_VOLTAGE: 10V@1A; CONFIGURATION: 1 Line; DEVICE_TYPENAME: D_ESD_NORM-TPD1E10B061LINEBI-DIRECTIONAL55V01UA6V10V1A12PF090-0243-000-090-0243-000; DRAWING: @P3449_B01_LIB.P3449_B01(SCH_1):PAGE20; MAX_REVERSE_LEAKAGE_CURRENT: 0.1uA; MAX_REVERSE_VOLTAGE: 5.5V; NV_NAME: TPD1E10B06; NV_PN: 090-0243-000; PACK_TYPE: NORM; PATH: I393; PHYS_PAGE: 20; POLARITY: Bi-Directional; ROT: 0; SEC: 1; VER: 2; XY: (-2200,1450)
J15 = HDR_1X4: ANGLE: 0; ASSEMBLY: FAN; CDS_LIB: electro_mechanic; CDS_PART_NAME: HDR_1X4_NORM-2WBA2542,MALE,2.54MM,0,NO,NO,YES,250 V,4 A,064-0400-000; CDS_PHYS_PART_NAME: HDR_1X4_NORM-2WBA2542,MALE,2.54MM,0,NO,NO,YES,250 V,4 A,064-0400-000-064-0400-000; CDS_SEC: 1; DEVICE_TYPENAME: HDR_1X4_NORM-2WBA2542MALE254MM0NONOYES250V4A064-0400-000-064-0400-000; DRAWING: @P3449_B01_LIB.P3449_B01(SCH_1):PAGE20; GENDER: MALE; LATCHING: YES; MAX_CURRENT: 4:00 上午; MAX_VOLTAGE: 250 V; NV_NAME: 2WBA2542; NV_PN: 064-0400-000; PACK_TYPE: NORM; PATH: I368; PHYS_PAGE: 20; PITCH: 2.54mm; REFLOW: NO; ROT: 0; SEC: 1; SEC_TYPE: NORM; SHROUDED: NO; VER: 1; XY: (-7100,5750)
J50 = HDR_1X12: ANGLE: 90; ASSEMBLY: AUTOMATION; CDS_LIB: electro_mechanic; CDS_PART_NAME: HDR_1X12_NORM-G2100CE04C-016-H,MALE,2.54MM,90,YES,NO,NO,125 V,3 A,074-0239-000; CDS_PHYS_PART_NAME: HDR_1X12_NORM-G2100CE04C-016-H,MALE,2.54MM,90,YES,NO,NO,125 V,3 A,074-0239-000-074-0239-000; CDS_SEC: 1; DEVICE_TYPENAME: HDR_1X12_NORM-G2100CE04C-016-HMALE254MM90YESNONO125V3A074-0239-000-074-0239-000; DRAWING: @P3449_B01_LIB.P3449_B01(SCH_1):PAGE20; GENDER: MALE; LATCHING: NO; MAX_CURRENT: 3:00 上午; MAX_VOLTAGE: 125 V; NV_NAME: G2100CE04C-016-H; NV_PN: 074-0239-000; PACK_TYPE: NORM; PATH: I425; PHYS_PAGE: 20; PITCH: 2.54mm; REFLOW: YES; ROT: 0; SEC: 1; SHROUDED: NO; VER: 1; XY: (-2400,3200)
Q45 = Q_FET_N_ENH#1: ASSEMBLY: FAN; CDS_LIB: discrete; CDS_PART_NAME: Q_FET_N_ENH_DFN1006-DMN26D0UFB4,20V,999MOHM@10V / 3000MOHM@4.5V / 4000MOHM@2.5V,0.14A,0.805A,10V,0.35W,999NC@10V / 0NC@4.5V / A; CDS_PHYS_PART_NAME: Q_FET_N_ENH_DFN1006-DMN26D0UFB4,20V,999MOHM@10V / 3000MOHM@4.5V / 4000MOHM@2.5V,0.14A,0.805A,10V,0.35W,999NC@10V / 0NC@4.5V / B; CDS_SEC: 1; CONTINUOUS_CURRENT: 0.14A; CaptureCellPackProp: Q_FET_N_ENH##1; DEVICE_TYPENAME: Q_FET_N_ENH_DFN1006-DMN26D0UFB420V999MOHM10V3000MOHM45V4000MOHM25V014A0805A10V035W999NC10V0NC45VB; DRAWING: @P3449_B01_LIB.P3449_B01(SCH_1):PAGE20; MAX_CURRENT: 0.805A; MAX_VOLTAGE: 20V; MAX_WATTAGE: 0.35W; NV_NAME: DMN26D0UFB4; NV_PN: 300-0868-000; PACK_TYPE: DFN1006; PATH: I369; PHYS_PAGE: 20; Q_G: 999nC@10V / 0nC@4.5V / 999nC@2.5V; ROT: 0; R_DS_ON: 999mohm@10V / 3000mohm@4.5V / 4000mohm@2.5V; SEC: 1; VER: 2; V_BE_GS: 10V; XY: (-8650,4800)
Q48 = Q_FET_N_ENH#1: ASSEMBLY: AUTOMATION; CDS_LIB: discrete; CDS_PART_NAME: Q_FET_N_ENH_DFN1006-DMN26D0UFB4,20V,999MOHM@10V / 3000MOHM@4.5V / 4000MOHM@2.5V,0.14A,0.805A,10V,0.35W,999NC@10V / 0NC@4.5V / A; CDS_PHYS_PART_NAME: Q_FET_N_ENH_DFN1006-DMN26D0UFB4,20V,999MOHM@10V / 3000MOHM@4.5V / 4000MOHM@2.5V,0.14A,0.805A,10V,0.35W,999NC@10V / 0NC@4.5V / B; CDS_SEC: 1; CONTINUOUS_CURRENT: 0.14A; CaptureCellPackProp: Q_FET_N_ENH##1; DEVICE_TYPENAME: Q_FET_N_ENH_DFN1006-DMN26D0UFB420V999MOHM10V3000MOHM45V4000MOHM25V014A0805A10V035W999NC10V0NC45VB; DRAWING: @P3449_B01_LIB.P3449_B01(SCH_1):PAGE20; MAX_CURRENT: 0.805A; MAX_VOLTAGE: 20V; MAX_WATTAGE: 0.35W; NV_NAME: DMN26D0UFB4; NV_PN: 300-0868-000; PACK_TYPE: DFN1006; PATH: I419; PHYS_PAGE: 20; Q_G: 999nC@10V / 0nC@4.5V / 999nC@2.5V; ROT: 0; R_DS_ON: 999mohm@10V / 3000mohm@4.5V / 4000mohm@2.5V; SEC: 1; VER: 2; V_BE_GS: 10V; XY: (-1250,2150)
R114 = R: ASSEMBLY: FAN; CDS_LIB: discrete; CDS_PART_NAME: R_0402-100K,1 %,62.5MW,195-0005-000; CDS_PHYS_PART_NAME: R_0402-100K,1 %,62.5MW,195-0005-000-100K,195-0005-000; CDS_SEC: 1; DEVICE_TYPENAME: R_0402-100K1625MW195-0005-000-100K195-0005-000; DRAWING: @P3449_B01_LIB.P3449_B01(SCH_1):PAGE20; MAX_WATTAGE: 62.5mW; NV_PN: 195-0005-000; PATH: I3; PHYS_PAGE: 20; ROT: 0; SEC: 1; SIGNAL_MODEL: nv_res; TOL: 1%; VER: 2; XY: (-10900,5450)
R155 = R: ASSEMBLY: L4T_EEPROM; CDS_LIB: discrete; CDS_PART_NAME: R_0402-10K,5 %,62.5MW,195-0486-000; CDS_PHYS_PART_NAME: R_0402-10K,5 %,62.5MW,195-0486-000-10K,195-0486-000; CDS_SEC: 1; DEVICE_TYPENAME: R_0402-10K5625MW195-0486-000-10K195-0486-000; DRAWING: @P3449_B01_LIB.P3449_B01(SCH_1):PAGE20; MAX_WATTAGE: 62.5mW; NV_PN: 195-0486-000; PATH: I348; PHYS_PAGE: 20; ROT: 2; SEC: 1; SIGNAL_MODEL: nv_res; SKU: NO STUFF; TOL: 5%; VER: 2; XY: (-3450,5550)
R156 = R: ASSEMBLY: L4T_EEPROM; CDS_LIB: discrete; CDS_PART_NAME: R_0402-10K,5 %,62.5MW,195-0486-000; CDS_PHYS_PART_NAME: R_0402-10K,5 %,62.5MW,195-0486-000-10K,195-0486-000; CDS_SEC: 1; DEVICE_TYPENAME: R_0402-10K5625MW195-0486-000-10K195-0486-000; DRAWING: @P3449_B01_LIB.P3449_B01(SCH_1):PAGE20; MAX_WATTAGE: 62.5mW; NV_PN: 195-0486-000; PATH: I343; PHYS_PAGE: 20; ROT: 2; SEC: 1; SIGNAL_MODEL: nv_res; TOL: 5%; VER: 2; XY: (-3450,6200)
R157 = R: ASSEMBLY: L4T_EEPROM; CDS_LIB: discrete; CDS_PART_NAME: R_0402-10K,5 %,62.5MW,195-0486-000; CDS_PHYS_PART_NAME: R_0402-10K,5 %,62.5MW,195-0486-000-10K,195-0486-000; CDS_SEC: 1; DEVICE_TYPENAME: R_0402-10K5625MW195-0486-000-10K195-0486-000; DRAWING: @P3449_B01_LIB.P3449_B01(SCH_1):PAGE20; MAX_WATTAGE: 62.5mW; NV_PN: 195-0486-000; PATH: I344; PHYS_PAGE: 20; ROT: 2; SEC: 1; SIGNAL_MODEL: nv_res; TOL: 5%; VER: 2; XY: (-3800,6200)
R158 = R: ASSEMBLY: L4T_EEPROM; CDS_LIB: discrete; CDS_PART_NAME: R_0402-10K,5 %,62.5MW,195-0486-000; CDS_PHYS_PART_NAME: R_0402-10K,5 %,62.5MW,195-0486-000-10K,195-0486-000; CDS_SEC: 1; DEVICE_TYPENAME: R_0402-10K5625MW195-0486-000-10K195-0486-000; DRAWING: @P3449_B01_LIB.P3449_B01(SCH_1):PAGE20; MAX_WATTAGE: 62.5mW; NV_PN: 195-0486-000; PATH: I346; PHYS_PAGE: 20; ROT: 2; SEC: 1; SIGNAL_MODEL: nv_res; TOL: 5%; VER: 2; XY: (-4100,6200)
R172 = R: ASSEMBLY: L4T_EEPROM; CDS_LIB: discrete; CDS_PART_NAME: R_0402-10K,5 %,62.5MW,195-0486-000; CDS_PHYS_PART_NAME: R_0402-10K,5 %,62.5MW,195-0486-000-10K,195-0486-000; CDS_SEC: 1; DEVICE_TYPENAME: R_0402-10K5625MW195-0486-000-10K195-0486-000; DRAWING: @P3449_B01_LIB.P3449_B01(SCH_1):PAGE20; MAX_WATTAGE: 62.5mW; NV_PN: 195-0486-000; PATH: I350; PHYS_PAGE: 20; ROT: 2; SEC: 1; SIGNAL_MODEL: nv_res; TOL: 5%; VER: 2; XY: (-4400,5600)
R403 = R#1: ASSEMBLY: DEBUG; CDS_LIB: discrete; CDS_PART_NAME: R_0402-100K,1 %,62.5MW,195-0005-000; CDS_PHYS_PART_NAME: R_0402-100K,1 %,62.5MW,195-0005-000-100K,195-0005-000; CDS_SEC: 1; CHIPS_PART_NAME: R; DEVICE_TYPENAME: R_0402-100K1625MW195-0005-000-100K195-0005-000; DRAWING: @P3449_B01_LIB.P3449_B01(SCH_1):PAGE20; MAX_WATTAGE: 62.5mW; NV_PN: 195-0005-000; PATH: I317; PHYS_PAGE: 20; ROT: 0; SEC: 1; SIGNAL_MODEL: nv_res; TOL: 1%; VER: 1; XY: (-10600,2000)
R404 = R#1: ASSEMBLY: DEBUG; CDS_LIB: discrete; CDS_PART_NAME: R_0402-0OHM,0.05 OHM,62.5MW,195-2655-000; CDS_PHYS_PART_NAME: R_0402-0OHM,0.05 OHM,62.5MW,195-2655-000-0OHM,195-2655-000; CDS_SEC: 1; CHIPS_PART_NAME: R; DEVICE_TYPENAME: R_0402-0OHM005OHM625MW195-2655-000-0OHM195-2655-000; DRAWING: @P3449_B01_LIB.P3449_B01(SCH_1):PAGE20; MAX_WATTAGE: 62.5mW; NV_PN: 195-2655-000; PATH: I318; PHYS_PAGE: 20; ROT: 0; SEC: 1; SIGNAL_MODEL: nv_res; TOL: 0.05 ohm; VER: 1; XY: (-10600,2150)
R436 = R: ASSEMBLY: DEBUG; CDS_LIB: discrete; CDS_PART_NAME: R_0402-100K,1 %,62.5MW,195-0005-000; CDS_PHYS_PART_NAME: R_0402-100K,1 %,62.5MW,195-0005-000-100K,195-0005-000; CDS_SEC: 1; DEVICE_TYPENAME: R_0402-100K1625MW195-0005-000-100K195-0005-000; DRAWING: @P3449_B01_LIB.P3449_B01(SCH_1):PAGE20; MAX_WATTAGE: 62.5mW; NV_PN: 195-0005-000; PATH: I367; PHYS_PAGE: 20; ROT: 0; SEC: 1; SIGNAL_MODEL: nv_res; TOL: 1%; VER: 2; XY: (-8150,2600)
R446 = R: ASSEMBLY: FAN; CDS_LIB: discrete; CDS_PART_NAME: R_0402-10K,5 %,62.5MW,195-0486-000; CDS_PHYS_PART_NAME: R_0402-10K,5 %,62.5MW,195-0486-000-10K,195-0486-000; CDS_SEC: 1; DEVICE_TYPENAME: R_0402-10K5625MW195-0486-000-10K195-0486-000; DRAWING: @P3449_B01_LIB.P3449_B01(SCH_1):PAGE20; MAX_WATTAGE: 62.5mW; NV_PN: 195-0486-000; PATH: I370; PHYS_PAGE: 20; ROT: 0; SEC: 1; SIGNAL_MODEL: nv_res; TOL: 5%; VER: 2; XY: (-9150,4600)
R447 = R: ASSEMBLY: FAN; CDS_LIB: discrete; CDS_PART_NAME: R_0402-10K,5 %,62.5MW,195-0486-000; CDS_PHYS_PART_NAME: R_0402-10K,5 %,62.5MW,195-0486-000-10K,195-0486-000; CDS_SEC: 1; DEVICE_TYPENAME: R_0402-10K5625MW195-0486-000-10K195-0486-000; DRAWING: @P3449_B01_LIB.P3449_B01(SCH_1):PAGE20; MAX_WATTAGE: 62.5mW; NV_PN: 195-0486-000; PATH: I372; PHYS_PAGE: 20; ROT: 0; SEC: 1; SIGNAL_MODEL: nv_res; TOL: 5%; VER: 2; XY: (-8350,5950)
R454 = R: ASSEMBLY: L4T_EEPROM; CDS_LIB: discrete; CDS_PART_NAME: R_0402-10K,5 %,62.5MW,195-0486-000; CDS_PHYS_PART_NAME: R_0402-10K,5 %,62.5MW,195-0486-000-10K,195-0486-000; CDS_SEC: 1; DEVICE_TYPENAME: R_0402-10K5625MW195-0486-000-10K195-0486-000; DRAWING: @P3449_B01_LIB.P3449_B01(SCH_1):PAGE20; MAX_WATTAGE: 62.5mW; NV_PN: 195-0486-000; PATH: I375; PHYS_PAGE: 20; ROT: 2; SEC: 1; SIGNAL_MODEL: nv_res; SKU: NO STUFF; TOL: 5%; VER: 2; XY: (-4100,5550)
R455 = R: ASSEMBLY: L4T_EEPROM; CDS_LIB: discrete; CDS_PART_NAME: R_0402-10K,5 %,62.5MW,195-0486-000; CDS_PHYS_PART_NAME: R_0402-10K,5 %,62.5MW,195-0486-000-10K,195-0486-000; CDS_SEC: 1; DEVICE_TYPENAME: R_0402-10K5625MW195-0486-000-10K195-0486-000; DRAWING: @P3449_B01_LIB.P3449_B01(SCH_1):PAGE20; MAX_WATTAGE: 62.5mW; NV_PN: 195-0486-000; PATH: I374; PHYS_PAGE: 20; ROT: 2; SEC: 1; SIGNAL_MODEL: nv_res; SKU: NO STUFF; TOL: 5%; VER: 2; XY: (-3800,5550)
R492 = R#1: ASSEMBLY: AUTOMATION; CDS_LIB: discrete; CDS_PART_NAME: R_0402-0OHM,0.05 OHM,62.5MW,195-2655-000; CDS_PHYS_PART_NAME: R_0402-0OHM,0.05 OHM,62.5MW,195-2655-000-0OHM,195-2655-000; CDS_SEC: 1; CHIPS_PART_NAME: R; DEVICE_TYPENAME: R_0402-0OHM005OHM625MW195-2655-000-0OHM195-2655-000; DRAWING: @P3449_B01_LIB.P3449_B01(SCH_1):PAGE20; MAX_WATTAGE: 62.5mW; NV_PN: 195-2655-000; PATH: I426; PHYS_PAGE: 20; ROT: 0; SEC: 1; SIGNAL_MODEL: nv_res; TOL: 0.05 ohm; VER: 1; XY: (-2100,2250)
R493 = R#1: ASSEMBLY: AUTOMATION; CDS_LIB: discrete; CDS_PART_NAME: R_0402-0OHM,0.05 OHM,62.5MW,195-2655-000; CDS_PHYS_PART_NAME: R_0402-0OHM,0.05 OHM,62.5MW,195-2655-000-0OHM,195-2655-000; CDS_SEC: 1; CHIPS_PART_NAME: R; DEVICE_TYPENAME: R_0402-0OHM005OHM625MW195-2655-000-0OHM195-2655-000; DRAWING: @P3449_B01_LIB.P3449_B01(SCH_1):PAGE20; MAX_WATTAGE: 62.5mW; NV_PN: 195-2655-000; PATH: I427; PHYS_PAGE: 20; ROT: 0; SEC: 1; SIGNAL_MODEL: nv_res; SKU: NO STUFF; TOL: 0.05 ohm; VER: 1; XY: (-2100,2100)
R494 = R: ASSEMBLY: AUTOMATION; CDS_LIB: discrete; CDS_PART_NAME: R_0402-10K,5 %,62.5MW,195-0486-000; CDS_PHYS_PART_NAME: R_0402-10K,5 %,62.5MW,195-0486-000-10K,195-0486-000; CDS_SEC: 1; DEVICE_TYPENAME: R_0402-10K5625MW195-0486-000-10K195-0486-000; DRAWING: @P3449_B01_LIB.P3449_B01(SCH_1):PAGE20; MAX_WATTAGE: 62.5mW; NV_PN: 195-0486-000; PATH: I430; PHYS_PAGE: 20; ROT: 0; SEC: 1; SIGNAL_MODEL: nv_res; TOL: 5%; VER: 2; XY: (-1600,2500)
R510 = R: ASSEMBLY: AUTOMATION; CDS_LIB: discrete; CDS_PART_NAME: R_0402-499OHM,1 %,62.5MW,195-0338-000; CDS_PHYS_PART_NAME: R_0402-499OHM,1 %,62.5MW,195-0338-000-195-0338-000,499OHM; CDS_SEC: 1; DEVICE_TYPENAME: R_0402-499OHM1625MW195-0338-000-195-0338-000499OHM; DRAWING: @P3449_B01_LIB.P3449_B01(SCH_1):PAGE20; MAX_WATTAGE: 62.5mW; NV_PN: 195-0338-000; PATH: I420; PHYS_PAGE: 20; ROT: 0; SEC: 1; SIGNAL_MODEL: nv_res; TOL: 1%; VER: 2; XY: (-1150,2750)
R516 = R: ASSEMBLY: FAN; CDS_LIB: discrete; CDS_PART_NAME: R_0402-100K,1 %,62.5MW,195-0005-000; CDS_PHYS_PART_NAME: R_0402-100K,1 %,62.5MW,195-0005-000-100K,195-0005-000; CDS_SEC: 1; DEVICE_TYPENAME: R_0402-100K1625MW195-0005-000-100K195-0005-000; DRAWING: @P3449_B01_LIB.P3449_B01(SCH_1):PAGE20; MAX_WATTAGE: 62.5mW; NV_PN: 195-0005-000; PATH: I439; PHYS_PAGE: 20; ROT: 0; SEC: 1; SIGNAL_MODEL: nv_res; TOL: 1%; VER: 2; XY: (-9250,5450)
TP19 = LABTESTPOINT#1: CDS_LIB: electro_mechanic; CDS_PART_NAME: LABTESTPOINT_PIN-LTPB071C125; CDS_PHYS_PART_NAME: LABTESTPOINT_PIN-LTPB071C125; CDS_SEC: 1; DEVICE_TYPENAME: LABTESTPOINT_PIN-LTPB071C125; DRAWING: @P3449_B01_LIB.P3449_B01(SCH_1):PAGE20; NV_NAME: LTPB071C125; PACK_TYPE: PIN; PATH: I337; PHYS_PAGE: 20; ROT: 0; SEC: 1; VER: 3; XY: (-1100,6000)
TP20 = LABTESTPOINT#1: CDS_LIB: electro_mechanic; CDS_PART_NAME: LABTESTPOINT_PIN-LTPB071C125; CDS_PHYS_PART_NAME: LABTESTPOINT_PIN-LTPB071C125; CDS_SEC: 1; DEVICE_TYPENAME: LABTESTPOINT_PIN-LTPB071C125; DRAWING: @P3449_B01_LIB.P3449_B01(SCH_1):PAGE20; NV_NAME: LTPB071C125; PACK_TYPE: PIN; PATH: I336; PHYS_PAGE: 20; ROT: 0; SEC: 1; VER: 3; XY: (-1100,6100)
U11 = U_MEM_EE_I2C: ASSEMBLY: L4T_EEPROM; CDS_LIB: memory; CDS_PART_NAME: U_MEM_EE_I2C_DFN08-1MHZ,1.7V..3.6V,AT24C02D-MAHM-T,174-0159-000; CDS_PHYS_PART_NAME: U_MEM_EE_I2C_DFN08-1MHZ,1.7V..3.6V,AT24C02D-MAHM-T,174-0159-000-174-0159-000; CDS_SEC: 1; DEVICE_TYPENAME: U_MEM_EE_I2C_DFN08-1MHZ17V36VAT24C02D-MAHM-T174-0159-000-174-0159-000; DRAWING: @P3449_B01_LIB.P3449_B01(SCH_1):PAGE20; NV_NAME: AT24C02D-MAHM-T; NV_PN: 174-0159-000; PACK_TYPE: DFN08; PATH: I335; PHYS_PAGE: 20; POW: 1.7V..3.6V; ROT: 0; SEC: 1; SEC_TYPE: DFN08; SPEED_GRADE: 1MHz; VER: 2; XY: (-3000,5750)
U52 = U_LEVSHFT_TXB0302: ASSEMBLY: DEBUG; CDS_LIB: logic; CDS_PART_NAME: U_LEVSHFT_TXB0302_DFN8-TXB0302DQMR,LEVEL SHIFTER,115-2177-000; CDS_PHYS_PART_NAME: U_LEVSHFT_TXB0302_DFN8-TXB0302DQMR,LEVEL SHIFTER,115-2177-000-115-2177-000; CDS_SEC: 1; DEVICE_TYPENAME: U_LEVSHFT_TXB0302_DFN8-TXB0302DQMRLEVELSHIFTER115-2177-000-115-2177-000; DRAWING: @P3449_B01_LIB.P3449_B01(SCH_1):PAGE20; FUNCTION: Level Shifter; NV_NAME: TXB0302DQMR; NV_PN: 115-2177-000; PATH: I365; PHYS_PAGE: 20; ROT: 0; SEC: 1; VER: 1; XY: (-8800,2300)
U68 = U_LEVSHFT_3STATE: ASSEMBLY: FAN; CDS_LIB: logic; CDS_PART_NAME: U_LEVSHFT_3STATE_SC70_6PIN-SN74LVC1T45DCKR-P,LEVEL SHIFTER,115-1968-000; CDS_PHYS_PART_NAME: U_LEVSHFT_3STATE_SC70_6PIN-SN74LVC1T45DCKR-P,LEVEL SHIFTER,115-1968-000-115-1968-000; CDS_SEC: 1; DEVICE_TYPENAME: U_LEVSHFT_3STATE_SC70_6PIN-SN74LVC1T45DCKR-PLEVELSHIFTER115-1968-000-115-1968-000; DRAWING: @P3449_B01_LIB.P3449_B01(SCH_1):PAGE20; FUNCTION: Level Shifter; NV_NAME: SN74LVC1T45DCKR-P; NV_PN: 115-1968-000; PACK_TYPE: SC70_6PIN; PATH: I435; PHYS_PAGE: 20; ROT: 2; SEC: 1; VER: 1; XY: (-9950,5600)
VS18 = VIRTUAL_SHORT#1: CDS_LIB: mechanic; CDS_PART_NAME: VIRTUAL_SHORT_SHUNT-VIRTUAL_SHORT; CDS_PHYS_PART_NAME: VIRTUAL_SHORT_SHUNT-VIRTUAL_SHORT; CDS_SEC: 1; DEVICE_TYPENAME: VIRTUAL_SHORT_SHUNT-VIRTUAL_SHORT; DRAWING: @P3449_B01_LIB.P3449_B01(SCH_1):PAGE20; PACK_TYPE: SHUNT; PATH: I424; PHYS_PAGE: 20; ROT: 0; SEC: 1; VER: 2; XY: (-5500,3550)
TP33 = LABTESTPOINT#1: CDS_LIB: electro_mechanic; CDS_PART_NAME: LABTESTPOINT_PIN-LTPB071C125; CDS_PHYS_PART_NAME: LABTESTPOINT_PIN-LTPB071C125; CDS_SEC: 1; DEVICE_TYPENAME: LABTESTPOINT_PIN-LTPB071C125; DRAWING: @P3449_B01_LIB.P3449_B01(SCH_1):PAGE21; NV_NAME: LTPB071C125; PACK_TYPE: PIN; PATH: I80; PHYS_PAGE: 21; ROT: 0; SEC: 1; VER: 3; XY: (-3100,4650)
TP34 = LABTESTPOINT#1: CDS_LIB: electro_mechanic; CDS_PART_NAME: LABTESTPOINT_PIN-LTPB071C125; CDS_PHYS_PART_NAME: LABTESTPOINT_PIN-LTPB071C125; CDS_SEC: 1; DEVICE_TYPENAME: LABTESTPOINT_PIN-LTPB071C125; DRAWING: @P3449_B01_LIB.P3449_B01(SCH_1):PAGE21; NV_NAME: LTPB071C125; PACK_TYPE: PIN; PATH: I85; PHYS_PAGE: 21; ROT: 0; SEC: 1; VER: 3; XY: (-3100,4550)
TP35 = LABTESTPOINT#1: CDS_LIB: electro_mechanic; CDS_PART_NAME: LABTESTPOINT_PIN-LTPB071C125; CDS_PHYS_PART_NAME: LABTESTPOINT_PIN-LTPB071C125; CDS_SEC: 1; DEVICE_TYPENAME: LABTESTPOINT_PIN-LTPB071C125; DRAWING: @P3449_B01_LIB.P3449_B01(SCH_1):PAGE21; NV_NAME: LTPB071C125; PACK_TYPE: PIN; PATH: I86; PHYS_PAGE: 21; ROT: 0; SEC: 1; VER: 3; XY: (-3100,4350)
TP36 = LABTESTPOINT#1: CDS_LIB: electro_mechanic; CDS_PART_NAME: LABTESTPOINT_PIN-LTPB071C125; CDS_PHYS_PART_NAME: LABTESTPOINT_PIN-LTPB071C125; CDS_SEC: 1; DEVICE_TYPENAME: LABTESTPOINT_PIN-LTPB071C125; DRAWING: @P3449_B01_LIB.P3449_B01(SCH_1):PAGE21; NV_NAME: LTPB071C125; PACK_TYPE: PIN; PATH: I87; PHYS_PAGE: 21; ROT: 0; SEC: 1; VER: 3; XY: (-3100,4250)
TP81 = LABTESTPOINT#1: CDS_LIB: electro_mechanic; CDS_PART_NAME: LABTESTPOINT_PIN-LTPB071C125; CDS_PHYS_PART_NAME: LABTESTPOINT_PIN-LTPB071C125; CDS_SEC: 1; DEVICE_TYPENAME: LABTESTPOINT_PIN-LTPB071C125; DRAWING: @P3449_B01_LIB.P3449_B01(SCH_1):PAGE21; NV_NAME: LTPB071C125; PACK_TYPE: PIN; PATH: I111; PHYS_PAGE: 21; ROT: 0; SEC: 1; VER: 3; XY: (-6750,5050)
TP82 = LABTESTPOINT#1: CDS_LIB: electro_mechanic; CDS_PART_NAME: LABTESTPOINT_PIN-LTPB071C125; CDS_PHYS_PART_NAME: LABTESTPOINT_PIN-LTPB071C125; CDS_SEC: 1; DEVICE_TYPENAME: LABTESTPOINT_PIN-LTPB071C125; DRAWING: @P3449_B01_LIB.P3449_B01(SCH_1):PAGE21; NV_NAME: LTPB071C125; PACK_TYPE: PIN; PATH: I110; PHYS_PAGE: 21; ROT: 0; SEC: 1; VER: 3; XY: (-6750,4950)
TP83 = LABTESTPOINT#1: CDS_LIB: electro_mechanic; CDS_PART_NAME: LABTESTPOINT_PIN-LTPB071C125; CDS_PHYS_PART_NAME: LABTESTPOINT_PIN-LTPB071C125; CDS_SEC: 1; DEVICE_TYPENAME: LABTESTPOINT_PIN-LTPB071C125; DRAWING: @P3449_B01_LIB.P3449_B01(SCH_1):PAGE21; NV_NAME: LTPB071C125; PACK_TYPE: PIN; PATH: I109; PHYS_PAGE: 21; ROT: 0; SEC: 1; VER: 3; XY: (-6750,4650)
TP84 = LABTESTPOINT#1: CDS_LIB: electro_mechanic; CDS_PART_NAME: LABTESTPOINT_PIN-LTPB071C125; CDS_PHYS_PART_NAME: LABTESTPOINT_PIN-LTPB071C125; CDS_SEC: 1; DEVICE_TYPENAME: LABTESTPOINT_PIN-LTPB071C125; DRAWING: @P3449_B01_LIB.P3449_B01(SCH_1):PAGE21; NV_NAME: LTPB071C125; PACK_TYPE: PIN; PATH: I108; PHYS_PAGE: 21; ROT: 0; SEC: 1; VER: 3; XY: (-6750,4550)
TP85 = LABTESTPOINT#1: CDS_LIB: electro_mechanic; CDS_PART_NAME: LABTESTPOINT_PIN-LTPB071C125; CDS_PHYS_PART_NAME: LABTESTPOINT_PIN-LTPB071C125; CDS_SEC: 1; DEVICE_TYPENAME: LABTESTPOINT_PIN-LTPB071C125; DRAWING: @P3449_B01_LIB.P3449_B01(SCH_1):PAGE21; NV_NAME: LTPB071C125; PACK_TYPE: PIN; PATH: I107; PHYS_PAGE: 21; ROT: 0; SEC: 1; VER: 3; XY: (-6750,4150)
TP86 = LABTESTPOINT#1: CDS_LIB: electro_mechanic; CDS_PART_NAME: LABTESTPOINT_PIN-LTPB071C125; CDS_PHYS_PART_NAME: LABTESTPOINT_PIN-LTPB071C125; CDS_SEC: 1; DEVICE_TYPENAME: LABTESTPOINT_PIN-LTPB071C125; DRAWING: @P3449_B01_LIB.P3449_B01(SCH_1):PAGE21; NV_NAME: LTPB071C125; PACK_TYPE: PIN; PATH: I106; PHYS_PAGE: 21; ROT: 0; SEC: 1; VER: 3; XY: (-6750,4050)
TP87 = LABTESTPOINT#1: CDS_LIB: electro_mechanic; CDS_PART_NAME: LABTESTPOINT_PIN-LTPB071C125; CDS_PHYS_PART_NAME: LABTESTPOINT_PIN-LTPB071C125; CDS_SEC: 1; DEVICE_TYPENAME: LABTESTPOINT_PIN-LTPB071C125; DRAWING: @P3449_B01_LIB.P3449_B01(SCH_1):PAGE21; NV_NAME: LTPB071C125; PACK_TYPE: PIN; PATH: I105; PHYS_PAGE: 21; ROT: 0; SEC: 1; VER: 3; XY: (-6750,3700)
TP88 = LABTESTPOINT#1: CDS_LIB: electro_mechanic; CDS_PART_NAME: LABTESTPOINT_PIN-LTPB071C125; CDS_PHYS_PART_NAME: LABTESTPOINT_PIN-LTPB071C125; CDS_SEC: 1; DEVICE_TYPENAME: LABTESTPOINT_PIN-LTPB071C125; DRAWING: @P3449_B01_LIB.P3449_B01(SCH_1):PAGE21; NV_NAME: LTPB071C125; PACK_TYPE: PIN; PATH: I104; PHYS_PAGE: 21; ROT: 0; SEC: 1; VER: 3; XY: (-6750,3600)
TP89 = LABTESTPOINT#1: CDS_LIB: electro_mechanic; CDS_PART_NAME: LABTESTPOINT_PIN-LTPB071C125; CDS_PHYS_PART_NAME: LABTESTPOINT_PIN-LTPB071C125; CDS_SEC: 1; DEVICE_TYPENAME: LABTESTPOINT_PIN-LTPB071C125; DRAWING: @P3449_B01_LIB.P3449_B01(SCH_1):PAGE21; NV_NAME: LTPB071C125; PACK_TYPE: PIN; PATH: I96; PHYS_PAGE: 21; ROT: 0; SEC: 1; VER: 3; XY: (-6750,3200)
TP90 = LABTESTPOINT#1: CDS_LIB: electro_mechanic; CDS_PART_NAME: LABTESTPOINT_PIN-LTPB071C125; CDS_PHYS_PART_NAME: LABTESTPOINT_PIN-LTPB071C125; CDS_SEC: 1; DEVICE_TYPENAME: LABTESTPOINT_PIN-LTPB071C125; DRAWING: @P3449_B01_LIB.P3449_B01(SCH_1):PAGE21; NV_NAME: LTPB071C125; PACK_TYPE: PIN; PATH: I97; PHYS_PAGE: 21; ROT: 0; SEC: 1; VER: 3; XY: (-6750,3100)
TP91 = LABTESTPOINT#1: CDS_LIB: electro_mechanic; CDS_PART_NAME: LABTESTPOINT_PIN-LTPB071C125; CDS_PHYS_PART_NAME: LABTESTPOINT_PIN-LTPB071C125; CDS_SEC: 1; DEVICE_TYPENAME: LABTESTPOINT_PIN-LTPB071C125; DRAWING: @P3449_B01_LIB.P3449_B01(SCH_1):PAGE21; NV_NAME: LTPB071C125; PACK_TYPE: PIN; PATH: I98; PHYS_PAGE: 21; ROT: 0; SEC: 1; VER: 3; XY: (-6750,2800)
TP92 = LABTESTPOINT#1: CDS_LIB: electro_mechanic; CDS_PART_NAME: LABTESTPOINT_PIN-LTPB071C125; CDS_PHYS_PART_NAME: LABTESTPOINT_PIN-LTPB071C125; CDS_SEC: 1; DEVICE_TYPENAME: LABTESTPOINT_PIN-LTPB071C125; DRAWING: @P3449_B01_LIB.P3449_B01(SCH_1):PAGE21; NV_NAME: LTPB071C125; PACK_TYPE: PIN; PATH: I99; PHYS_PAGE: 21; ROT: 0; SEC: 1; VER: 3; XY: (-6750,2700)
TP93 = LABTESTPOINT#1: CDS_LIB: electro_mechanic; CDS_PART_NAME: LABTESTPOINT_PIN-LTPB071C125; CDS_PHYS_PART_NAME: LABTESTPOINT_PIN-LTPB071C125; CDS_SEC: 1; DEVICE_TYPENAME: LABTESTPOINT_PIN-LTPB071C125; DRAWING: @P3449_B01_LIB.P3449_B01(SCH_1):PAGE21; NV_NAME: LTPB071C125; PACK_TYPE: PIN; PATH: I100; PHYS_PAGE: 21; ROT: 0; SEC: 1; VER: 3; XY: (-6750,2300)
TP94 = LABTESTPOINT#1: CDS_LIB: electro_mechanic; CDS_PART_NAME: LABTESTPOINT_PIN-LTPB071C125; CDS_PHYS_PART_NAME: LABTESTPOINT_PIN-LTPB071C125; CDS_SEC: 1; DEVICE_TYPENAME: LABTESTPOINT_PIN-LTPB071C125; DRAWING: @P3449_B01_LIB.P3449_B01(SCH_1):PAGE21; NV_NAME: LTPB071C125; PACK_TYPE: PIN; PATH: I101; PHYS_PAGE: 21; ROT: 0; SEC: 1; VER: 3; XY: (-6750,2200)
TP95 = LABTESTPOINT#1: CDS_LIB: electro_mechanic; CDS_PART_NAME: LABTESTPOINT_PIN-LTPB071C125; CDS_PHYS_PART_NAME: LABTESTPOINT_PIN-LTPB071C125; CDS_SEC: 1; DEVICE_TYPENAME: LABTESTPOINT_PIN-LTPB071C125; DRAWING: @P3449_B01_LIB.P3449_B01(SCH_1):PAGE21; NV_NAME: LTPB071C125; PACK_TYPE: PIN; PATH: I102; PHYS_PAGE: 21; ROT: 0; SEC: 1; VER: 3; XY: (-6750,1850)
TP96 = LABTESTPOINT#1: CDS_LIB: electro_mechanic; CDS_PART_NAME: LABTESTPOINT_PIN-LTPB071C125; CDS_PHYS_PART_NAME: LABTESTPOINT_PIN-LTPB071C125; CDS_SEC: 1; DEVICE_TYPENAME: LABTESTPOINT_PIN-LTPB071C125; DRAWING: @P3449_B01_LIB.P3449_B01(SCH_1):PAGE21; NV_NAME: LTPB071C125; PACK_TYPE: PIN; PATH: I103; PHYS_PAGE: 21; ROT: 0; SEC: 1; VER: 3; XY: (-6750,1750)

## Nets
GND: C61.2 C102.2 C136.2 C137.2 C293.2 C294.2 C295.1 C297.2 C314.2 D37.2 D38.2 D39.2 D40.2 D44.2 D45.2 D47.2 D48.2 J15.1 J41.6 J41.9 J41.14 J41.20 J41.25 J41.30 J41.34 J41.39 J50.7 J50.9 J50.11 Q48.2(S) R114.2 R155.2 R172.2 R203.1 R368.1 R370.1 R403.1 R454.2 R455.2 R516.2 U7.11(GND) U7.21(EP) U11.4(GND) U11.9(TP) U22.11(GND) U22.21(EP) U48.11(GND) U48.21(EP) U52.4(GND) U68.2(GND) U68.5(DIR) ; also on sheet 4 5 6 7 8 9 10 11 12 13 14 15 18 22
VDD_1V8: C102.1 C136.1 C295.2 Q45.1(G) R156.1 R157.1 R158.1 R204.1 R367.1 R369.1 R404.1 R446.1 R494.1 U7.2(VCCA) U11.8(VCC) U22.2(VCCA) U48.2(VCCA) U52.1(VCCA) U68.6(VCCB) ; also on sheet 5 6 8 10 18
VDD_3V3_SYS: C137.1 C293.1 C297.1 J41.1 J41.17 R436.1 R437.1 R438.1 U7.19(VCCB) U22.19(VCCB) U48.19(VCCB) U52.8(VCCB) ; also on sheet 4 5 6 7 8 10 17 18
VDD_5V_IN: C61.1 C294.1 J15.2 J41.2 J41.4 R447.1 U68.1(VCCA) VS18.1(A) ; also on sheet 6 9 10 11 13 14 18
BOARD_ID_A0: R155.1 R156.2 U11.1(A0)
BOARD_ID_WP: R172.1 U11.7(WP)
BRD_ID_A1: R157.2 R455.1 U11.2(A1)
BRD_ID_A2: R158.2 R454.1 U11.3(A2)
FAN_PWM: R114.1 U68.4(B) ; also on sheet 17
FAN_PWM_Q*: J15.4 R516.1 U68.3(A)
FAN_TACH: Q45.2(S) R446.2 ; also on sheet 17
FAN_TACH_CON: J15.3 Q45.3(D) R447.2
FORCE_RECOVERY*: J50.10 ; also on sheet 18
GPIO01: U48.9(A8) ; also on sheet 17
GPIO01_LS: J41.29 U48.12(B8)
GPIO07: U22.7(A6) ; also on sheet 17
GPIO07_LS: J41.32 U22.14(B6)
GPIO09: U48.6(A5) ; also on sheet 17
GPIO09_LS: J41.7 U48.15(B5)
GPIO11: U48.8(A7) ; also on sheet 17
GPIO11_LS: J41.31 U48.13(B7)
GPIO12: U22.8(A7) ; also on sheet 17
GPIO12_LS: J41.15 U22.13(B7)
GPIO13: U48.7(A6) ; also on sheet 17
GPIO13_LS: J41.33 U48.14(B6)
I2C1_SCL: D39.1 J41.5 ; also on sheet 18
I2C1_SDA: D40.1 J41.3 ; also on sheet 18
I2C2_SCL: TP20.1 U11.6(SCL) ; also on sheet 8 18
I2C2_SDA: TP19.1 U11.5(SDA) ; also on sheet 8 18
I2S0_LRCK: U48.5(A4) ; also on sheet 17
I2S0_LRCK_LS: J41.35 U48.16(B4)
I2S0_SCLK: U48.1(A1) ; also on sheet 17
I2S0_SCLK_LS: J41.12 U48.20(B1)
I2S0_SDIN: U48.4(A3) ; also on sheet 17
I2S0_SDIN_LS: J41.38 U48.17(B3)
I2S0_SDOUT: U48.3(A2) ; also on sheet 17
I2S0_SDOUT_LS: J41.40 U48.18(B2)
ID_I2C_SCL: D37.1 J41.28 ; also on sheet 18
ID_I2C_SDA: D38.1 J41.27 ; also on sheet 18
LATCH_SET: D45.1 J50.5 ; also on sheet 9
LATCH_SET_BUT: D44.1 J50.6 ; also on sheet 9
LED1_CTRL: Q48.1(G) R492.2 R493.2 R494.2
MOD_SLEEP*: R493.1 ; also on sheet 6 18
PC_LED+: J50.2 VS18.2(B)
PC_LED-: J50.1 R510.1
PC_LED_R: Q48.3(D) R510.2
PCIE0_RX1_N: TP92.1 ; also on sheet 16
PCIE0_RX1_P: TP91.1 ; also on sheet 16
PCIE0_RX2_N: TP94.1 ; also on sheet 16
PCIE0_RX2_P: TP93.1 ; also on sheet 16
PCIE0_RX3_N: TP96.1 ; also on sheet 16
PCIE0_RX3_P: TP95.1 ; also on sheet 16
PCIE0_TX1_N: TP86.1 ; also on sheet 16
PCIE0_TX1_P: TP85.1 ; also on sheet 16
PCIE0_TX2_N: TP84.1 ; also on sheet 16
PCIE0_TX2_P: TP83.1 ; also on sheet 16
PCIE0_TX3_N: TP82.1 ; also on sheet 16
PCIE0_TX3_P: TP81.1 ; also on sheet 16
PCIE1_CLK_N: TP36.1 ; also on sheet 16
PCIE1_CLK_P: TP35.1 ; also on sheet 16
PCIE1_CLKREQ: TP34.1 ; also on sheet 16
PCIE1_RST: TP33.1 ; also on sheet 16
PCIE1_RX0_N: TP90.1 ; also on sheet 16
PCIE1_RX0_P: TP89.1 ; also on sheet 16
PCIE1_TX0_N: TP88.1 ; also on sheet 16
PCIE1_TX0_P: TP87.1 ; also on sheet 16
PWR_BTN*: J50.12 ; also on sheet 9 18
PWR_LED_CTRL: R492.1 ; also on sheet 17 18
SPI0_CS0: U22.5(A4) ; also on sheet 17
SPI0_CS0_LS: J41.24 U22.16(B4)
SPI0_CS1: U22.6(A5) ; also on sheet 17
SPI0_CS1_LS: J41.26 U22.15(B5)
SPI0_MISO: U22.3(A2) ; also on sheet 17
SPI0_MISO_LS: J41.21 U22.18(B2)
SPI0_MOSI: U22.4(A3) ; also on sheet 17
SPI0_MOSI_LS: J41.19 U22.17(B3)
SPI0_SCK: U22.1(A1) ; also on sheet 17
SPI0_SCK_LS: J41.23 U22.20(B1)
SPI1_CS0: U7.5(A4) ; also on sheet 17
SPI1_CS0_LS: J41.18 U7.16(B4)
SPI1_CS1: U7.6(A5) ; also on sheet 17
SPI1_CS1_LS: J41.16 U7.15(B5)
SPI1_MISO: U7.3(A2) ; also on sheet 17
SPI1_MISO_LS: J41.22 U7.18(B2)
SPI1_MOSI: U7.4(A3) ; also on sheet 17
SPI1_MOSI_LS: J41.37 U7.17(B3)
SPI1_SCK: U7.1(A1) ; also on sheet 17
SPI1_SCK_LS: J41.13 U7.20(B1)
SYS_RST*: C314.1 J50.8 ; also on sheet 10 18
TXL8_1_OE: R203.2 R204.2 U22.10(OE)
TXL8_2_OE: R367.2 R368.2 U48.10(OE)
TXL8_3_OE: R369.2 R370.2 U7.10(OE)
U52_OUTPUT_EN: R403.2 R404.2 U52.5(OE)
UART1_CTS: U7.9(A8) ; also on sheet 18
UART1_CTS_LS: J41.36 R438.2 U7.12(B8)
UART1_RTS: U22.9(A8) ; also on sheet 18
UART1_RTS_LS: J41.11 U22.12(B8)
UART1_RXD: U7.8(A7) ; also on sheet 18
UART1_RXD_LS: J41.10 R437.2 U7.13(B7)
UART1_TXD: U7.7(A6) ; also on sheet 18
UART1_TXD_LS: J41.8 U7.14(B6)
UART2_RXD: U52.2(A1) ; also on sheet 18
UART2_RXD_LS: D47.1 J50.3 R436.2 U52.7(B1)
UART2_TXD: U52.3(A2) ; also on sheet 18
UART2_TXD_LS: D48.1 J50.4 U52.6(B2)

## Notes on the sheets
sheet 1
- A
- B
- C
- D
- E
- F
- G
- H
- PROVISION FOR LOOP BACK TEST OF UNUSED PCIe SIGNALS
- 1
- 1
- 2
- PCIe LOOP BACK TO TEST UNUSED PCIe SIGNALS
- 2
- PLACE TESTPOINT ON THE BOTTOM OF THE BOARD
- 3
- 3
- PLACE ALL TESTPOINTS ON THE BOTTOM OF THE BOARD
- FOR TEST ONLY!!!
- 4
- 4
- 5
- 5
- NVIDIA CORPORATION
- 2701 SAN TOMAS
  EXPRESSWAY
- ASSEMBLY
- Jetson Nano Carrier Board
- SANTA CLARA, CA 95050, USA
- PAGE DETAIL
- Loop Back
  Test
- NV_PN
- ALL NVIDIA DESIGN SPECIFICATIONS, REFERENCE SPECIFICATIONS, REFERENCE BOARDS, FILES, DRAWINGS, DIAGNOSTICS, LISTS AND OTHER DOCUMENTS OR INFORMATION (TOGETHER AND SEPARATELY, 'MATERIALS') ARE BEING PROVIDED 'AS IS'. THE MATERIALS
  MAY
- CONTAIN KNOWN AND UNKNOWN VIOLATIONS OR DEVIATIONS OF INDUSTRY STANDARDS AND SPECIFICATIONS. NVIDIA MAKES NO WARRANTIES, EXPRESSED, IMPLIED, STATUTORY OR OTHERWISE WITH RESPECT TO THE MATERIALS OR OTHERWISE, AND EXPRESSLY DISCLAIMS
  ALL
- PCB REV
- PAGE
- 21 OF 23
- IMPLIED WARRANTIES INCLUDING, WITHOUT LIMITATION, THE WARRANTIES OF DESIGN, OF NONINFRINGEMENT, MERCHANTABILITY OR FITNESS FOR A PARTICULAR PURPOSE, OR ARISING FROM A COURSE OF DEALING, TRADE USAGE, TRADE PRACTICE, OR INDUSTRY
  STANDARDS.
- BOM REV
- A
- DATE
- 08-MAY-2019
- A
- B
- C
- D
- E
- F
- G
- H
sheet 2
- A
- B
- C
- D
- E
- F
- G
- H
- SoC Fan Header 4pin
- Carrier board config
- 1
- 1
- GND
- PWR
- TACH
- PWM
- 7'b1010xxx
- 7'b1010111 = 7'h57
- 2
- 2
- Vgs(th) = 0.45 to 1.05V
- Optional Button Header Pinout
- 3
- Serial Port
- 3
- 4
- 4
- 5
- 5
- NVIDIA CORPORATION
- 2701 SAN TOMAS
  EXPRESSWAY
- ASSEMBLY
- Jetson Nano Carrier Board
- SANTA CLARA, CA 95050, USA
- PAGE DETAIL
- Fan, Debug and EEPROM
- NV_PN
- ALL NVIDIA DESIGN SPECIFICATIONS, REFERENCE SPECIFICATIONS, REFERENCE BOARDS, FILES, DRAWINGS, DIAGNOSTICS, LISTS AND OTHER DOCUMENTS OR INFORMATION (TOGETHER AND SEPARATELY, 'MATERIALS') ARE BEING PROVIDED 'AS IS'. THE MATERIALS
  MAY
- CONTAIN KNOWN AND UNKNOWN VIOLATIONS OR DEVIATIONS OF INDUSTRY STANDARDS AND SPECIFICATIONS. NVIDIA MAKES NO WARRANTIES, EXPRESSED, IMPLIED, STATUTORY OR OTHERWISE WITH RESPECT TO THE MATERIALS OR OTHERWISE, AND EXPRESSLY DISCLAIMS
  ALL
- PCB REV
- PAGE
- 20 OF 23
- IMPLIED WARRANTIES INCLUDING, WITHOUT LIMITATION, THE WARRANTIES OF DESIGN, OF NONINFRINGEMENT, MERCHANTABILITY OR FITNESS FOR A PARTICULAR PURPOSE, OR ARISING FROM A COURSE OF DEALING, TRADE USAGE, TRADE PRACTICE, OR INDUSTRY
  STANDARDS.
- BOM REV
- A
- DATE
- 08-MAY-2019
- A
- B
- C
- D
- E
- F
- G
- H
sheet 3
- A
- B
- C
- D
- E
- F
- G
- H
- 40PIN GPIO EXPANSION HEADER & LEVEL SHIFTERS
- 1
- 1
- Place close to U22, U48, U7
- 2
- 2
- 3
- 3
- 40pin HDR
- 4
- 4
- 5
- 5
- NVIDIA CORPORATION
- 2701 SAN TOMAS
  EXPRESSWAY
- ASSEMBLY
- Jetson Nano Carrier Board
- SANTA CLARA, CA 95050, USA
- PAGE DETAIL
- 40Pin GPIO expansion
  header
- NV_PN
- ALL NVIDIA DESIGN SPECIFICATIONS, REFERENCE SPECIFICATIONS, REFERENCE BOARDS, FILES, DRAWINGS, DIAGNOSTICS, LISTS AND OTHER DOCUMENTS OR INFORMATION (TOGETHER AND SEPARATELY, 'MATERIALS') ARE BEING PROVIDED 'AS IS'. THE MATERIALS
  MAY
- CONTAIN KNOWN AND UNKNOWN VIOLATIONS OR DEVIATIONS OF INDUSTRY STANDARDS AND SPECIFICATIONS. NVIDIA MAKES NO WARRANTIES, EXPRESSED, IMPLIED, STATUTORY OR OTHERWISE WITH RESPECT TO THE MATERIALS OR OTHERWISE, AND EXPRESSLY DISCLAIMS
  ALL
- PCB REV
- PAGE
- 19 OF 23
- IMPLIED WARRANTIES INCLUDING, WITHOUT LIMITATION, THE WARRANTIES OF DESIGN, OF NONINFRINGEMENT, MERCHANTABILITY OR FITNESS FOR A PARTICULAR PURPOSE, OR ARISING FROM A COURSE OF DEALING, TRADE USAGE, TRADE PRACTICE, OR INDUSTRY
  STANDARDS.
- BOM REV
- A
- DATE
- 08-MAY-2019
- A
- B
- C
- D
- E
- F
- G
- H
